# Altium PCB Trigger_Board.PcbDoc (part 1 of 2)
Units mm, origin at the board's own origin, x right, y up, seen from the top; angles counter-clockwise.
Board outline 80 x 80 mm, 4 copper layers (Component Side, Signal Layer 1, Signal Layer 2, Bottom Layer), stack 0.651 mm thick; 190 components, 73 nets, 468 pads, 398 vias.
Unrouted connection lines stored in the file: 444.
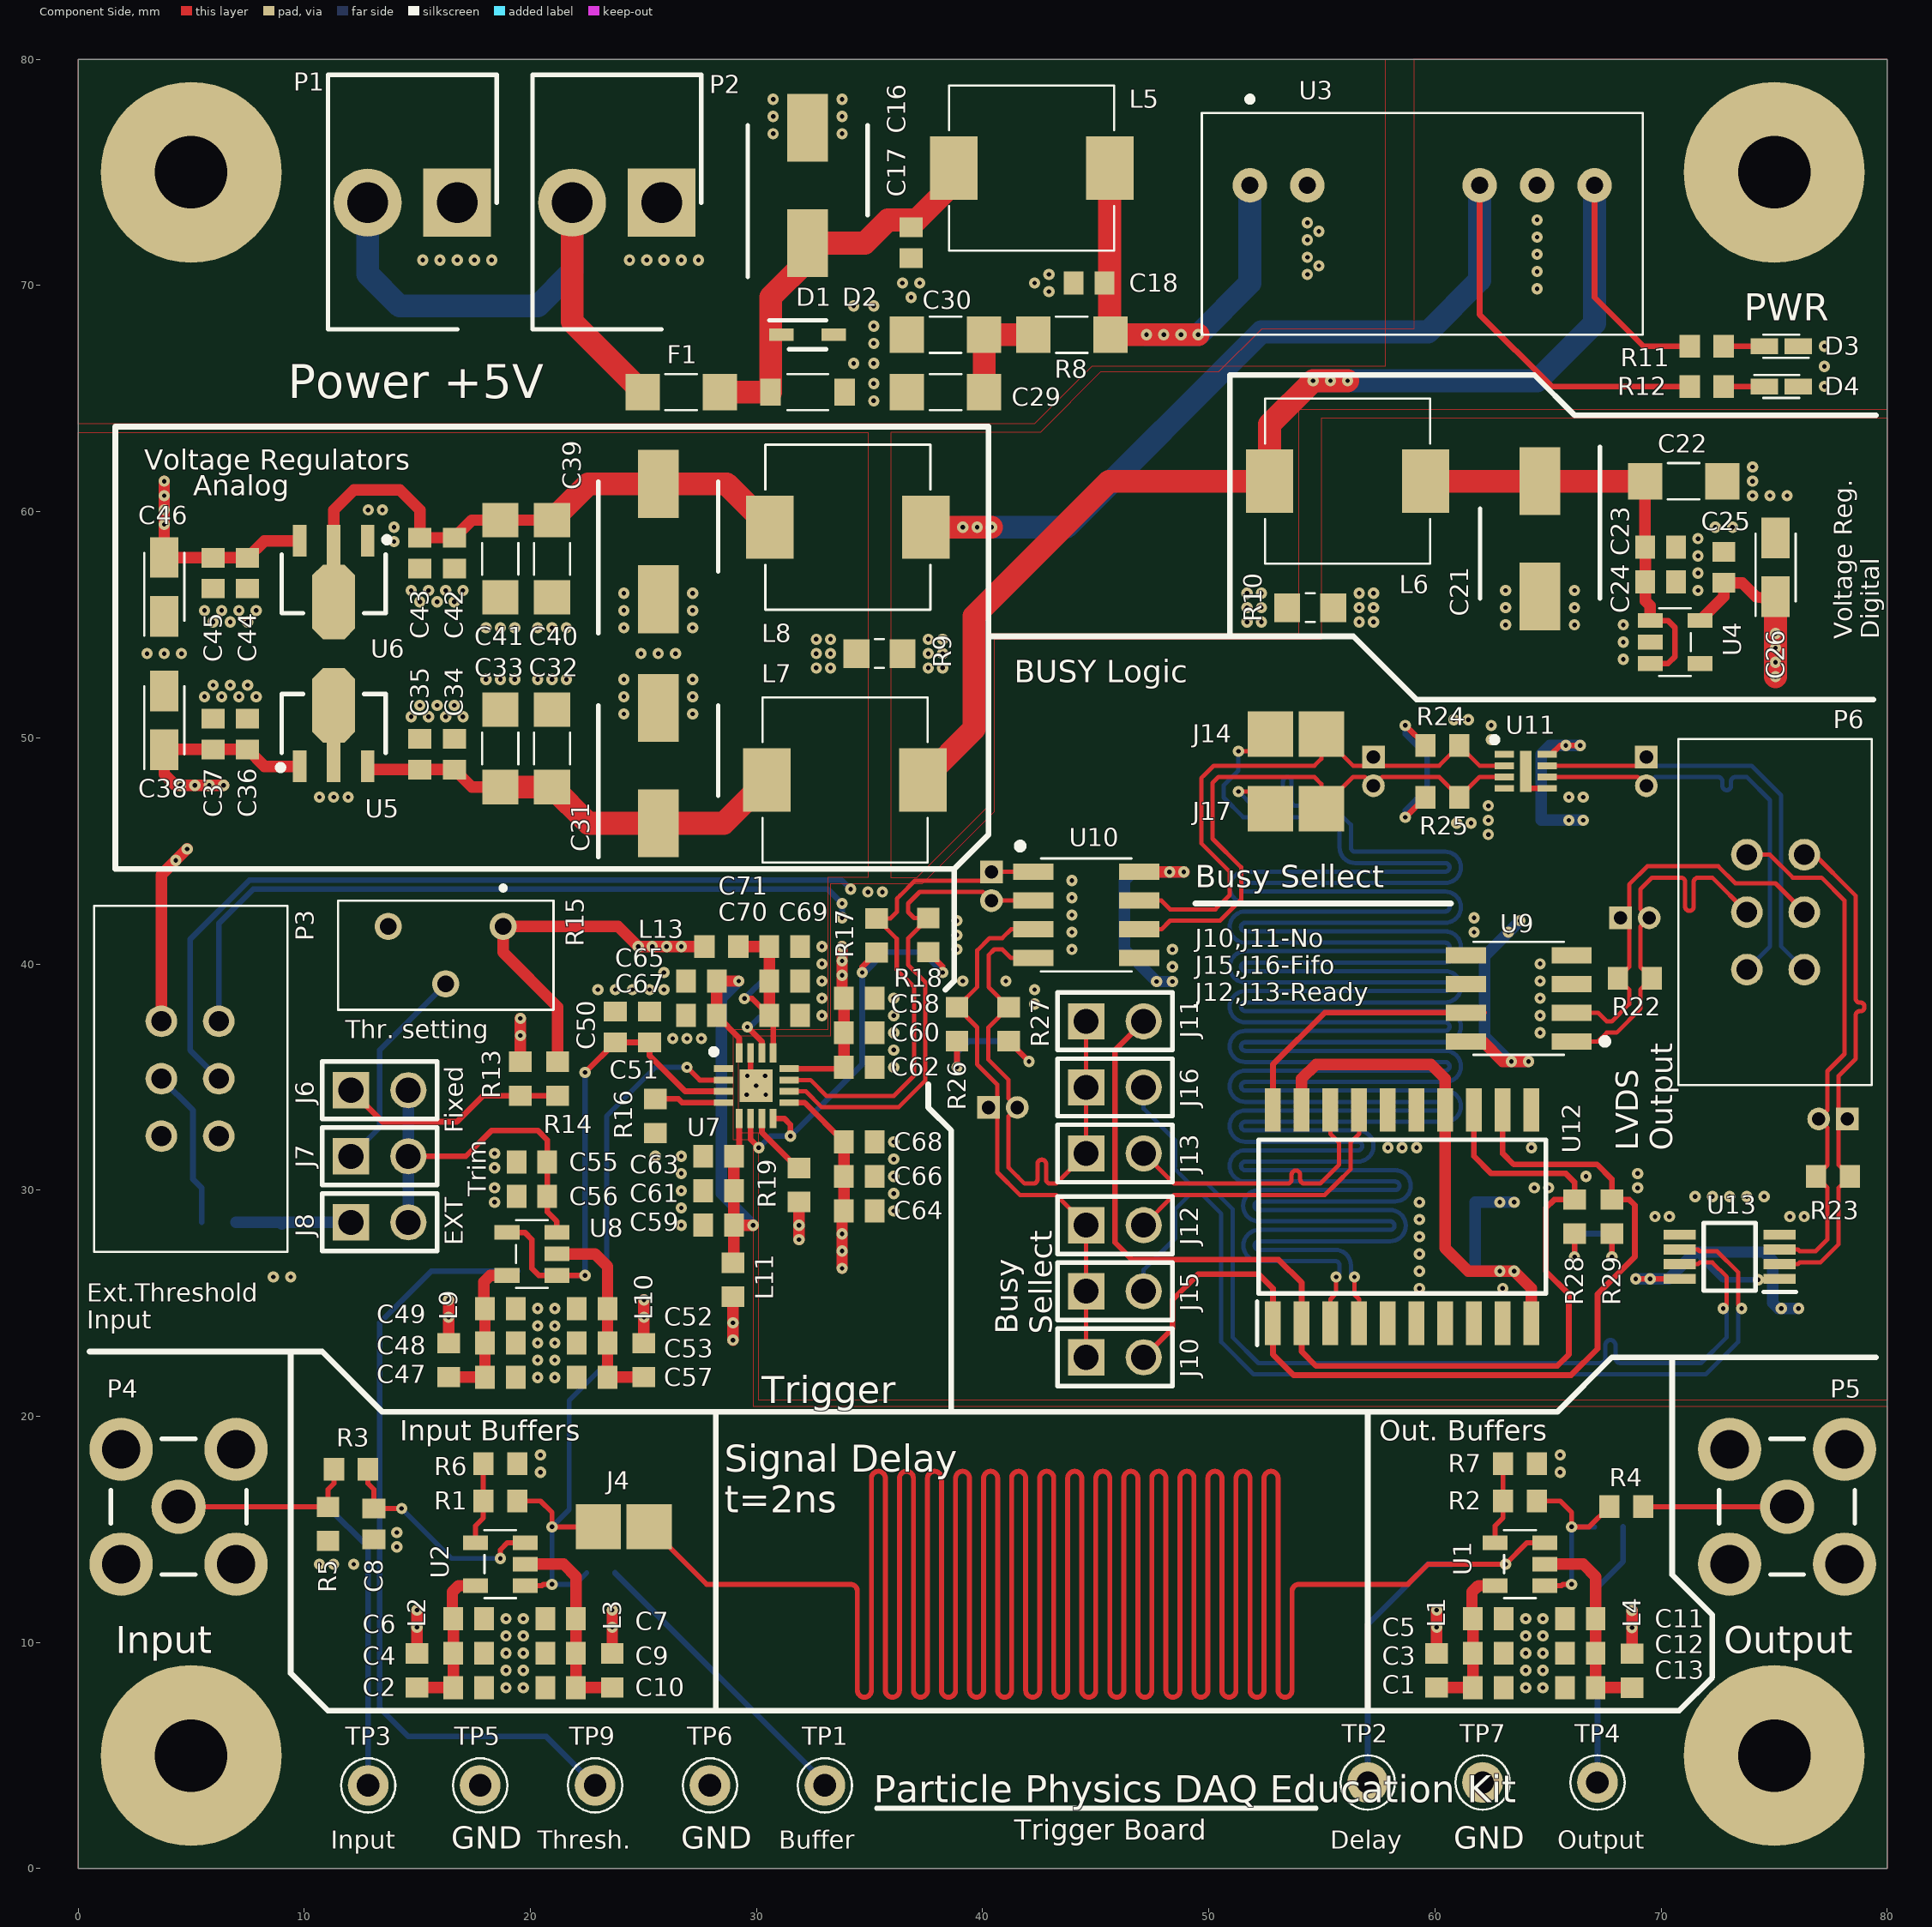
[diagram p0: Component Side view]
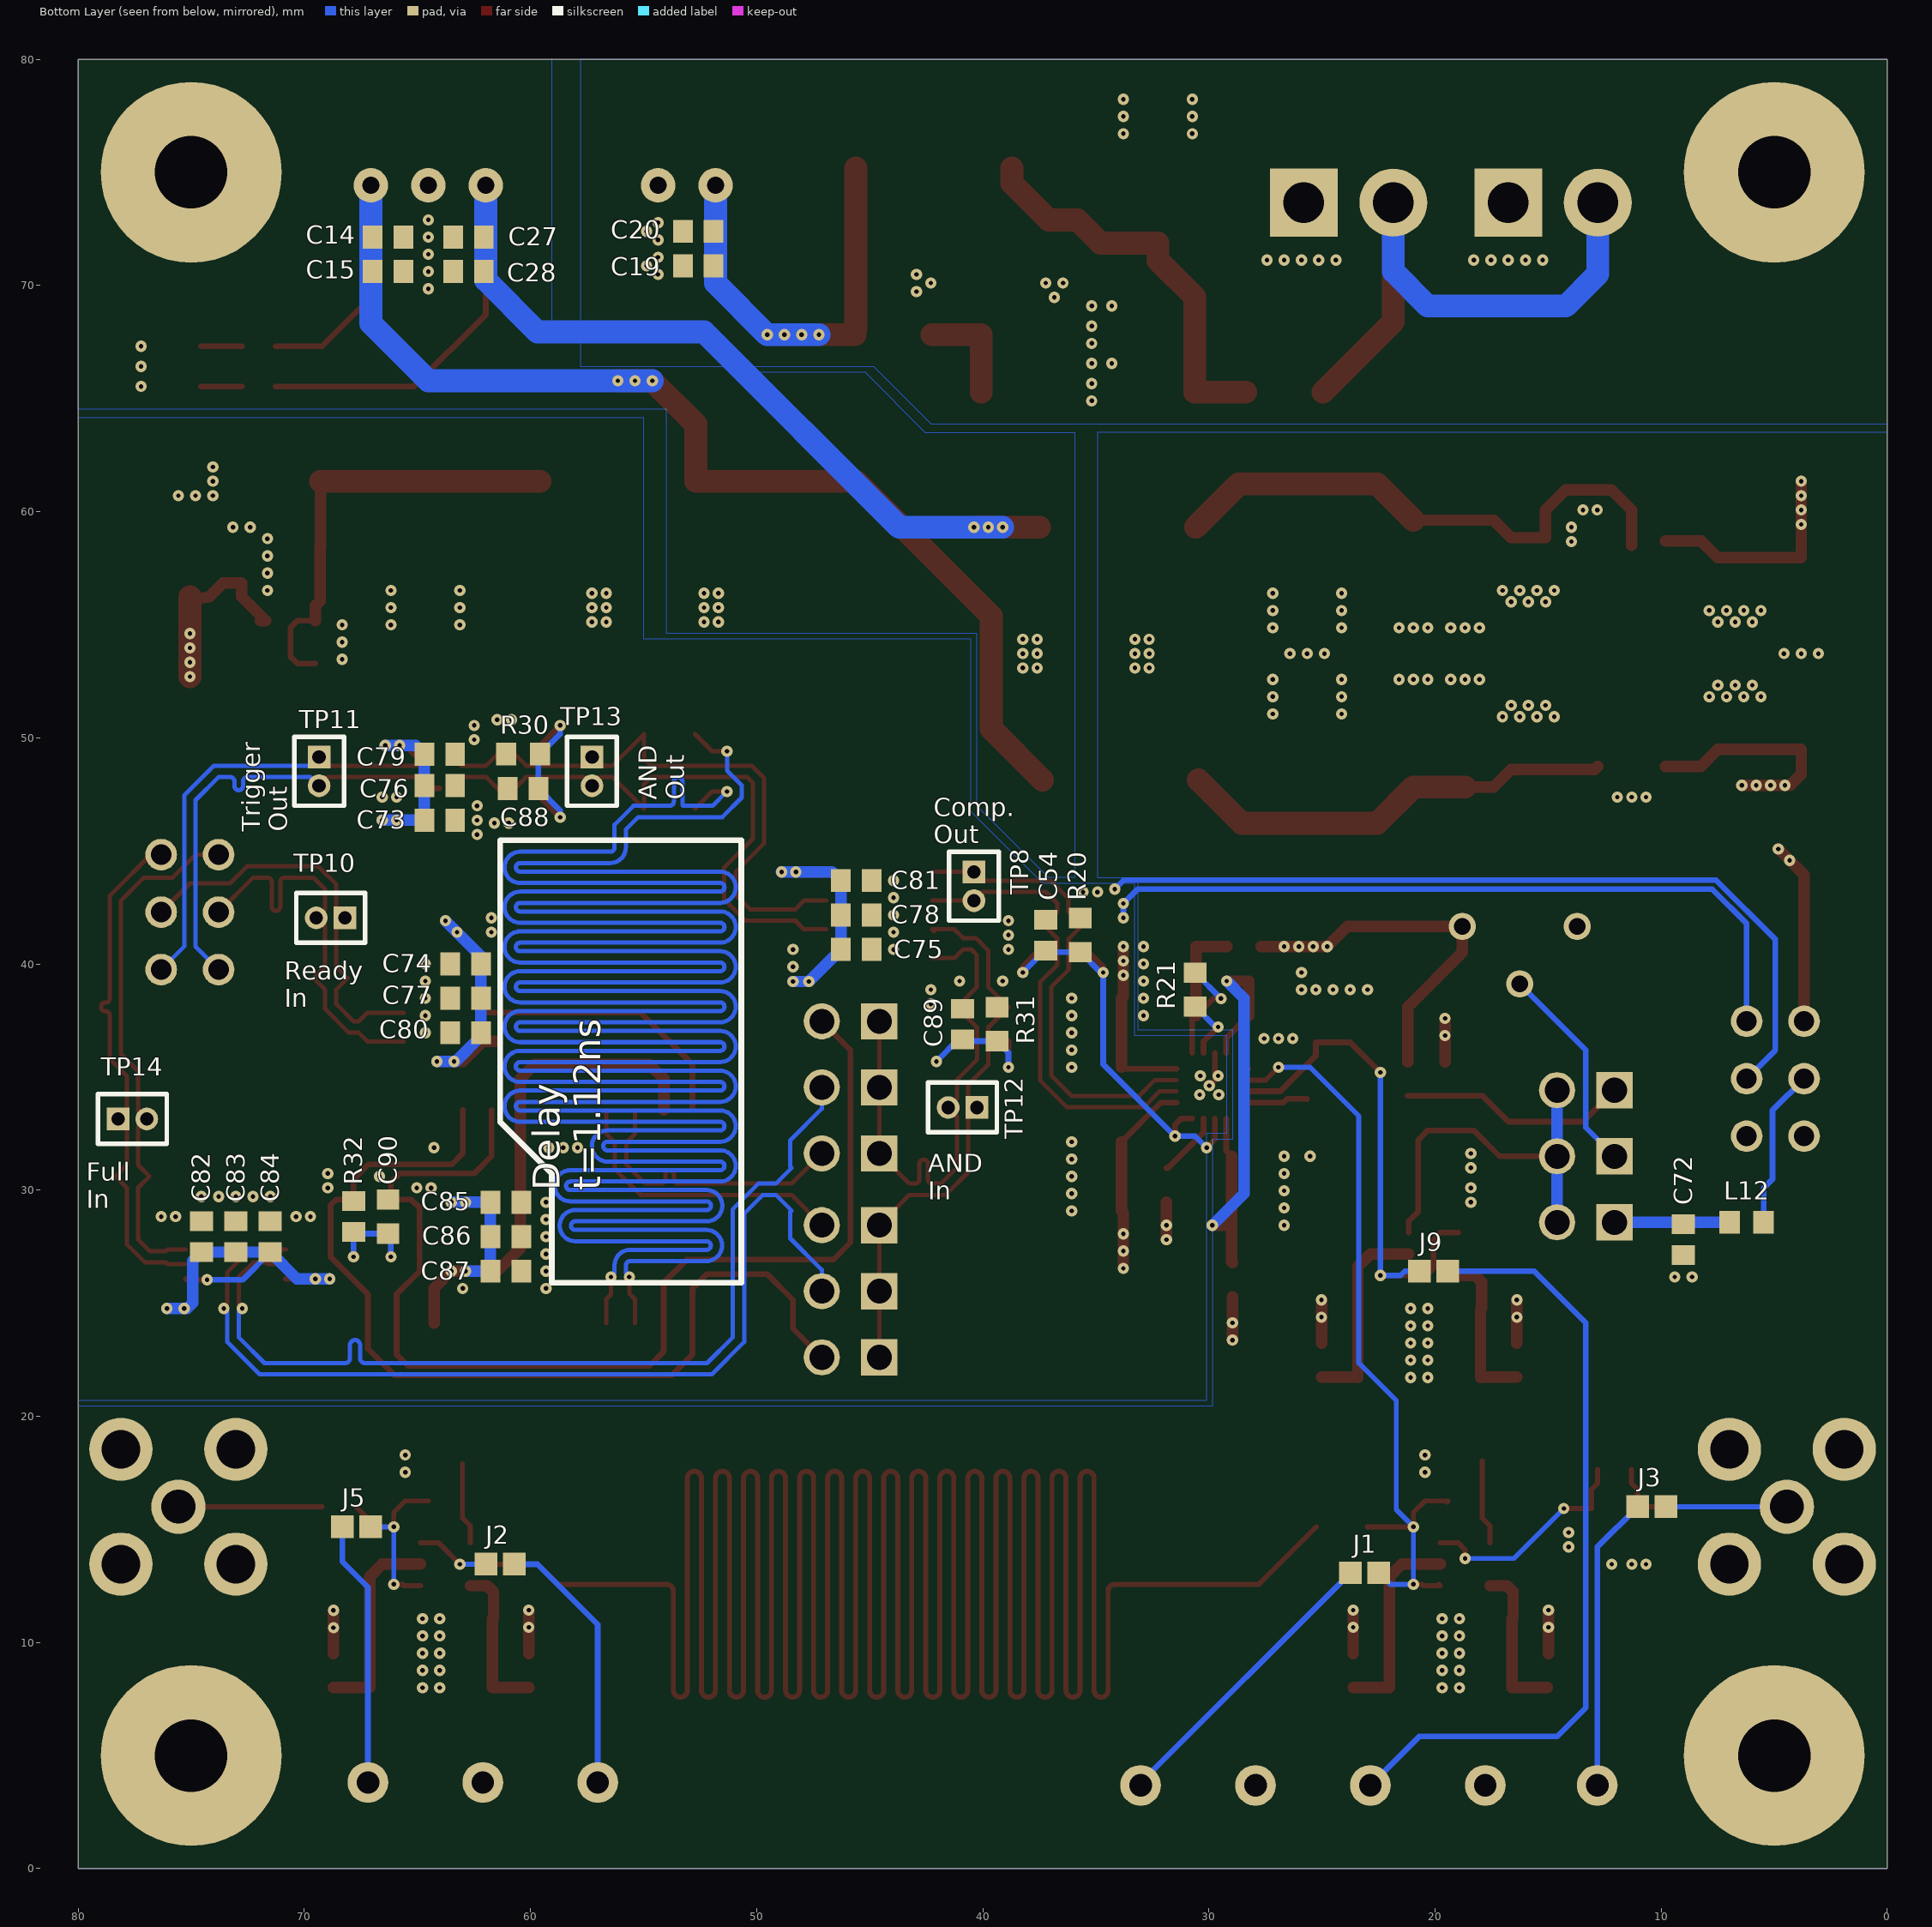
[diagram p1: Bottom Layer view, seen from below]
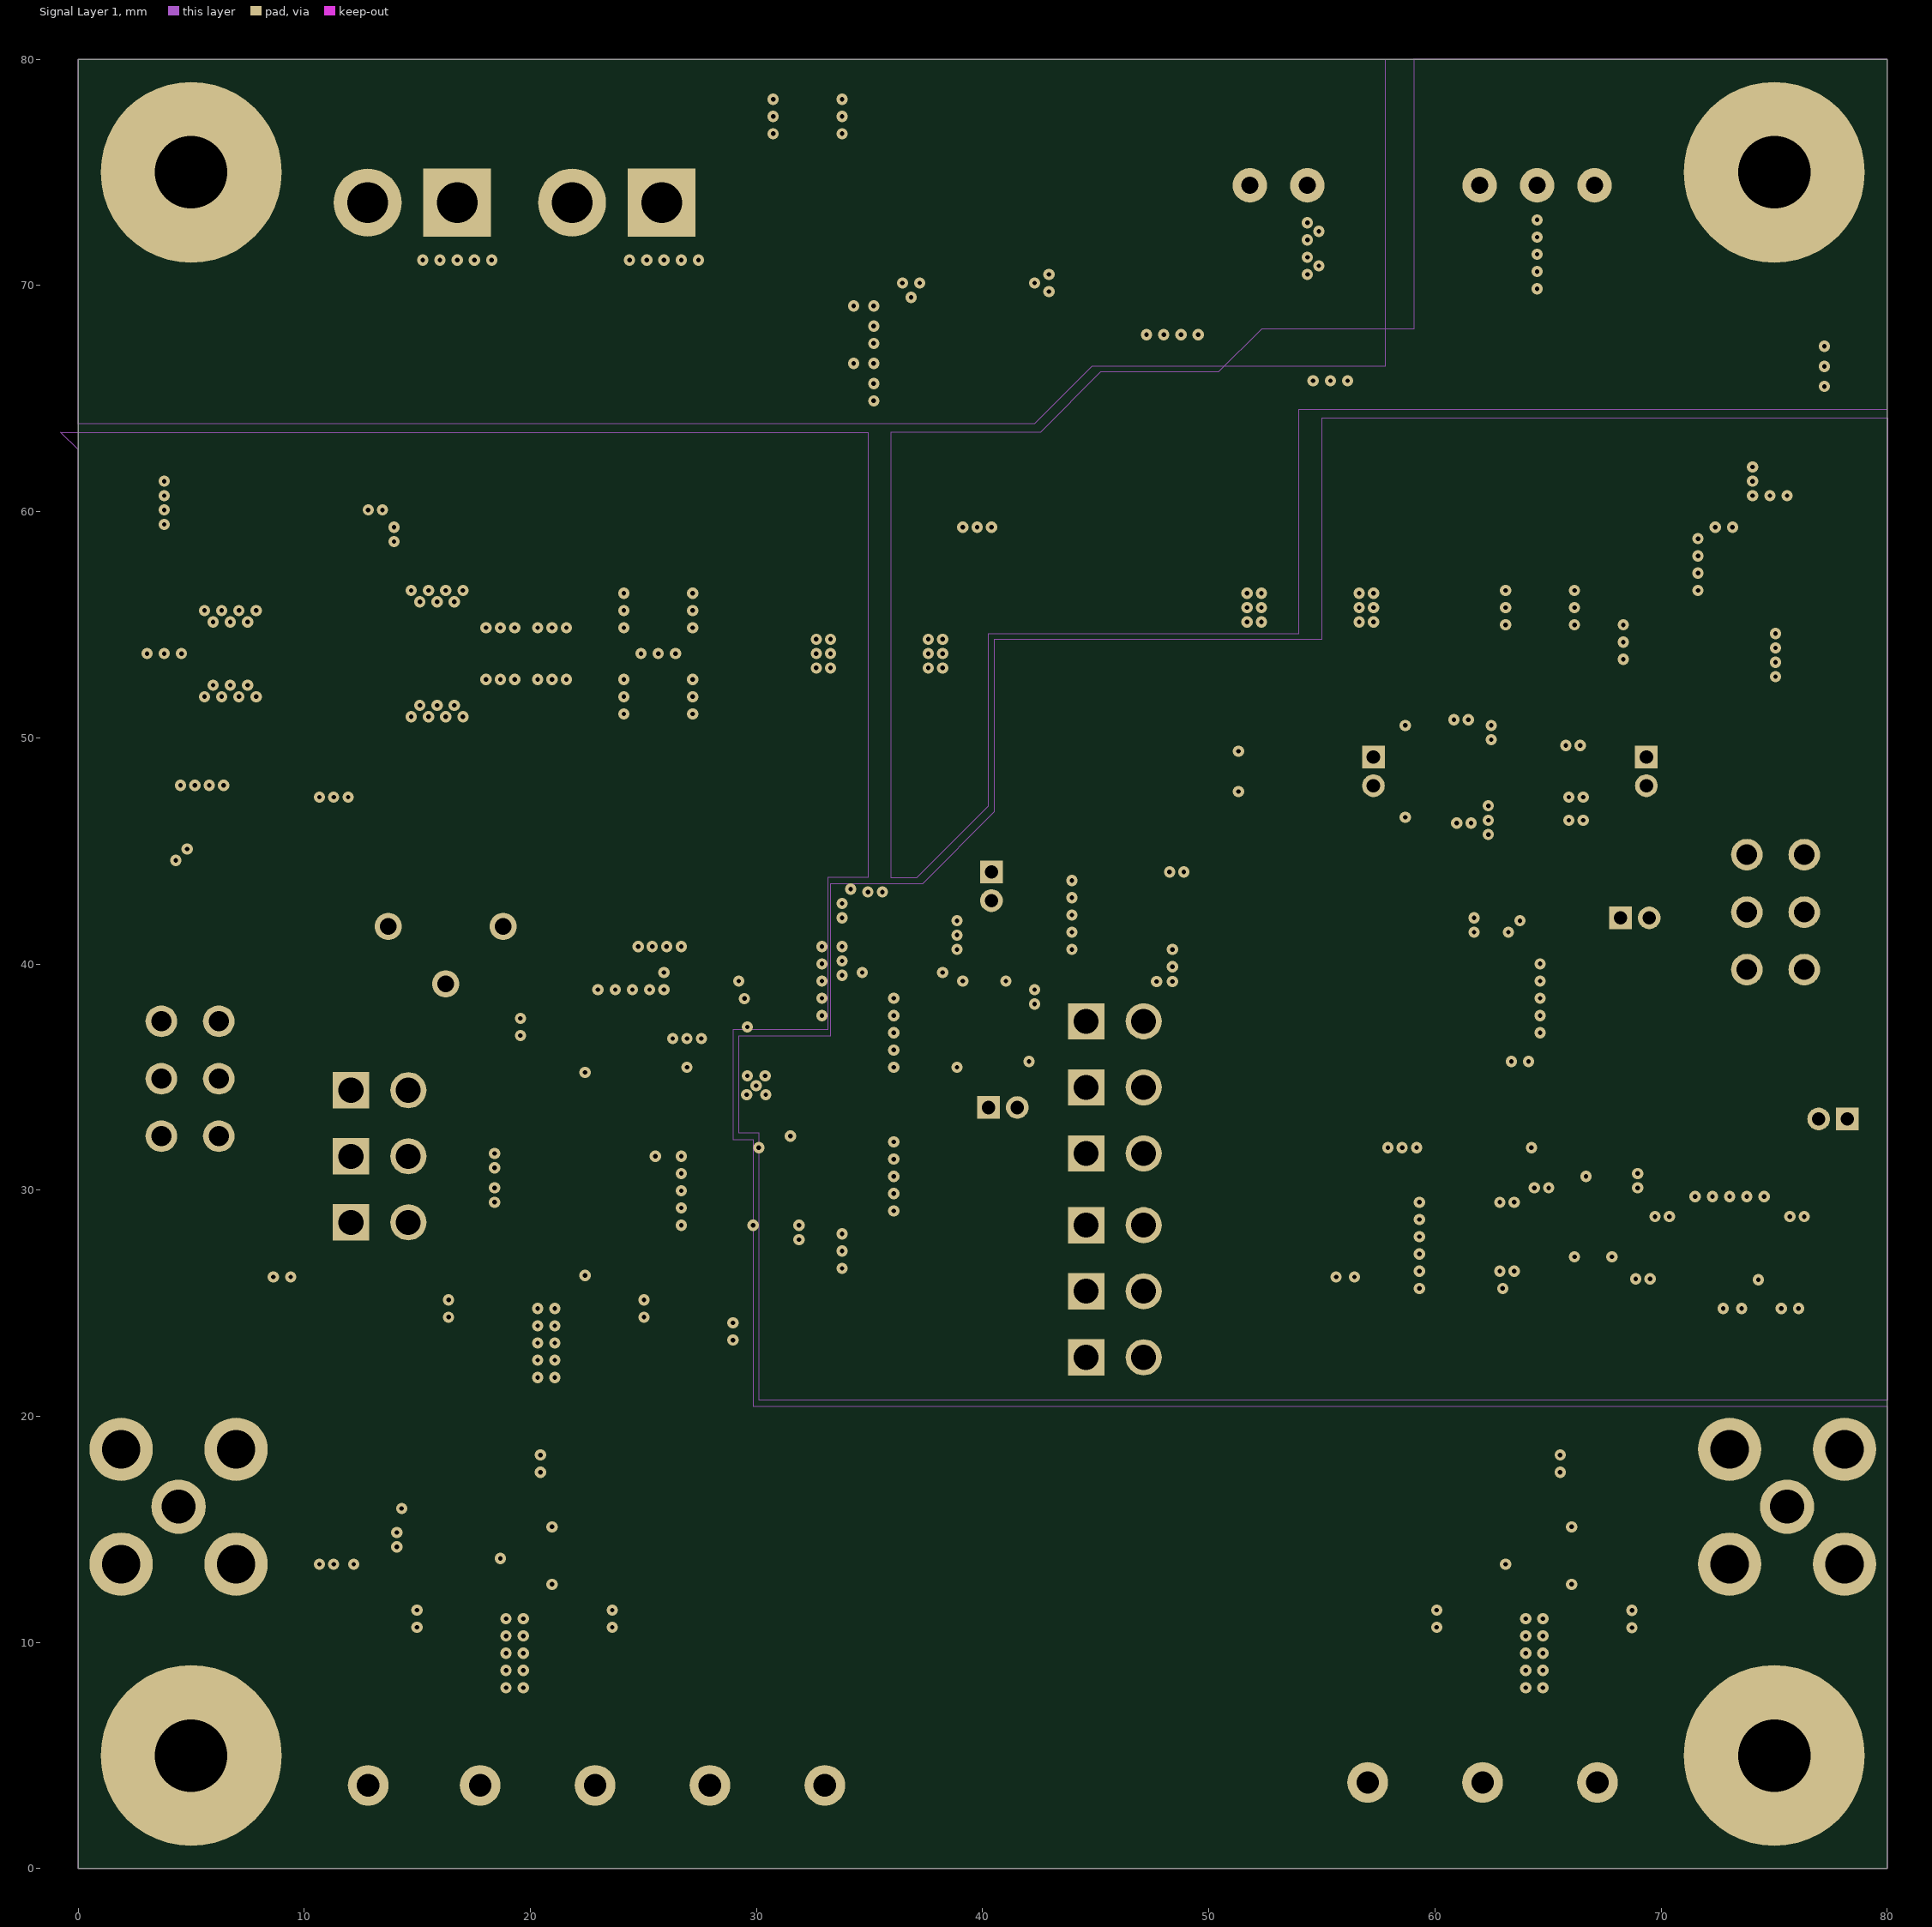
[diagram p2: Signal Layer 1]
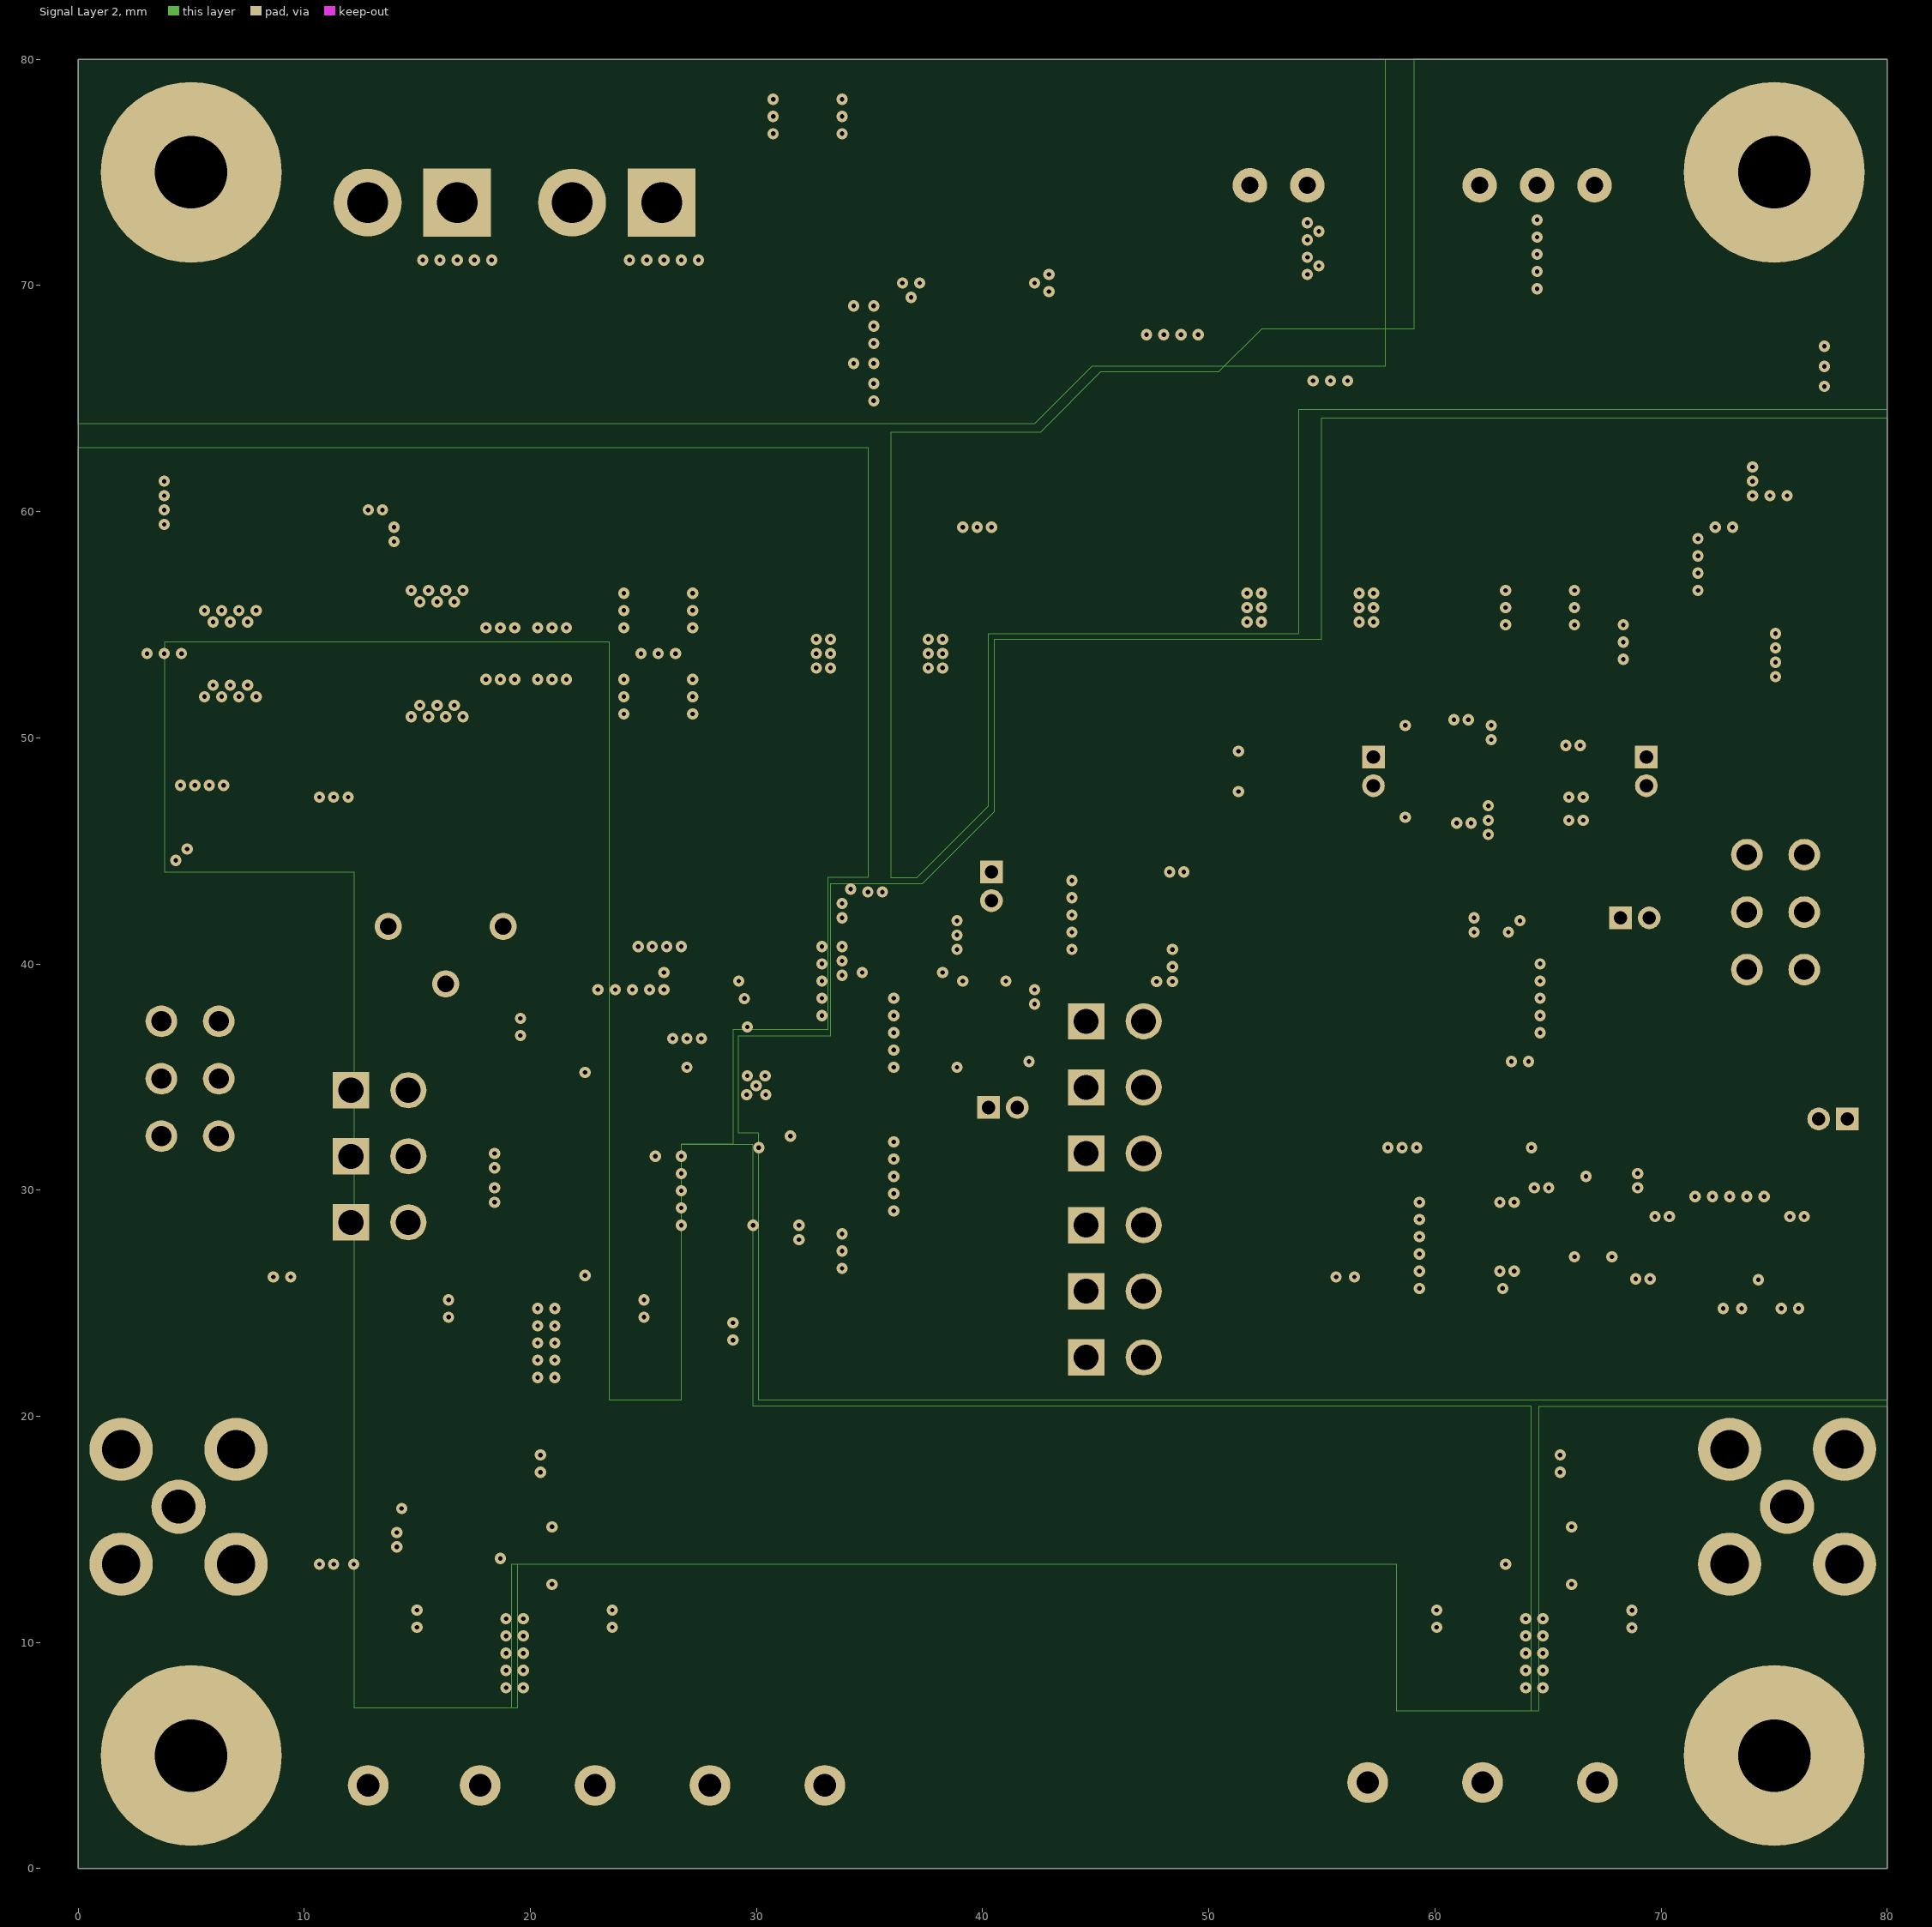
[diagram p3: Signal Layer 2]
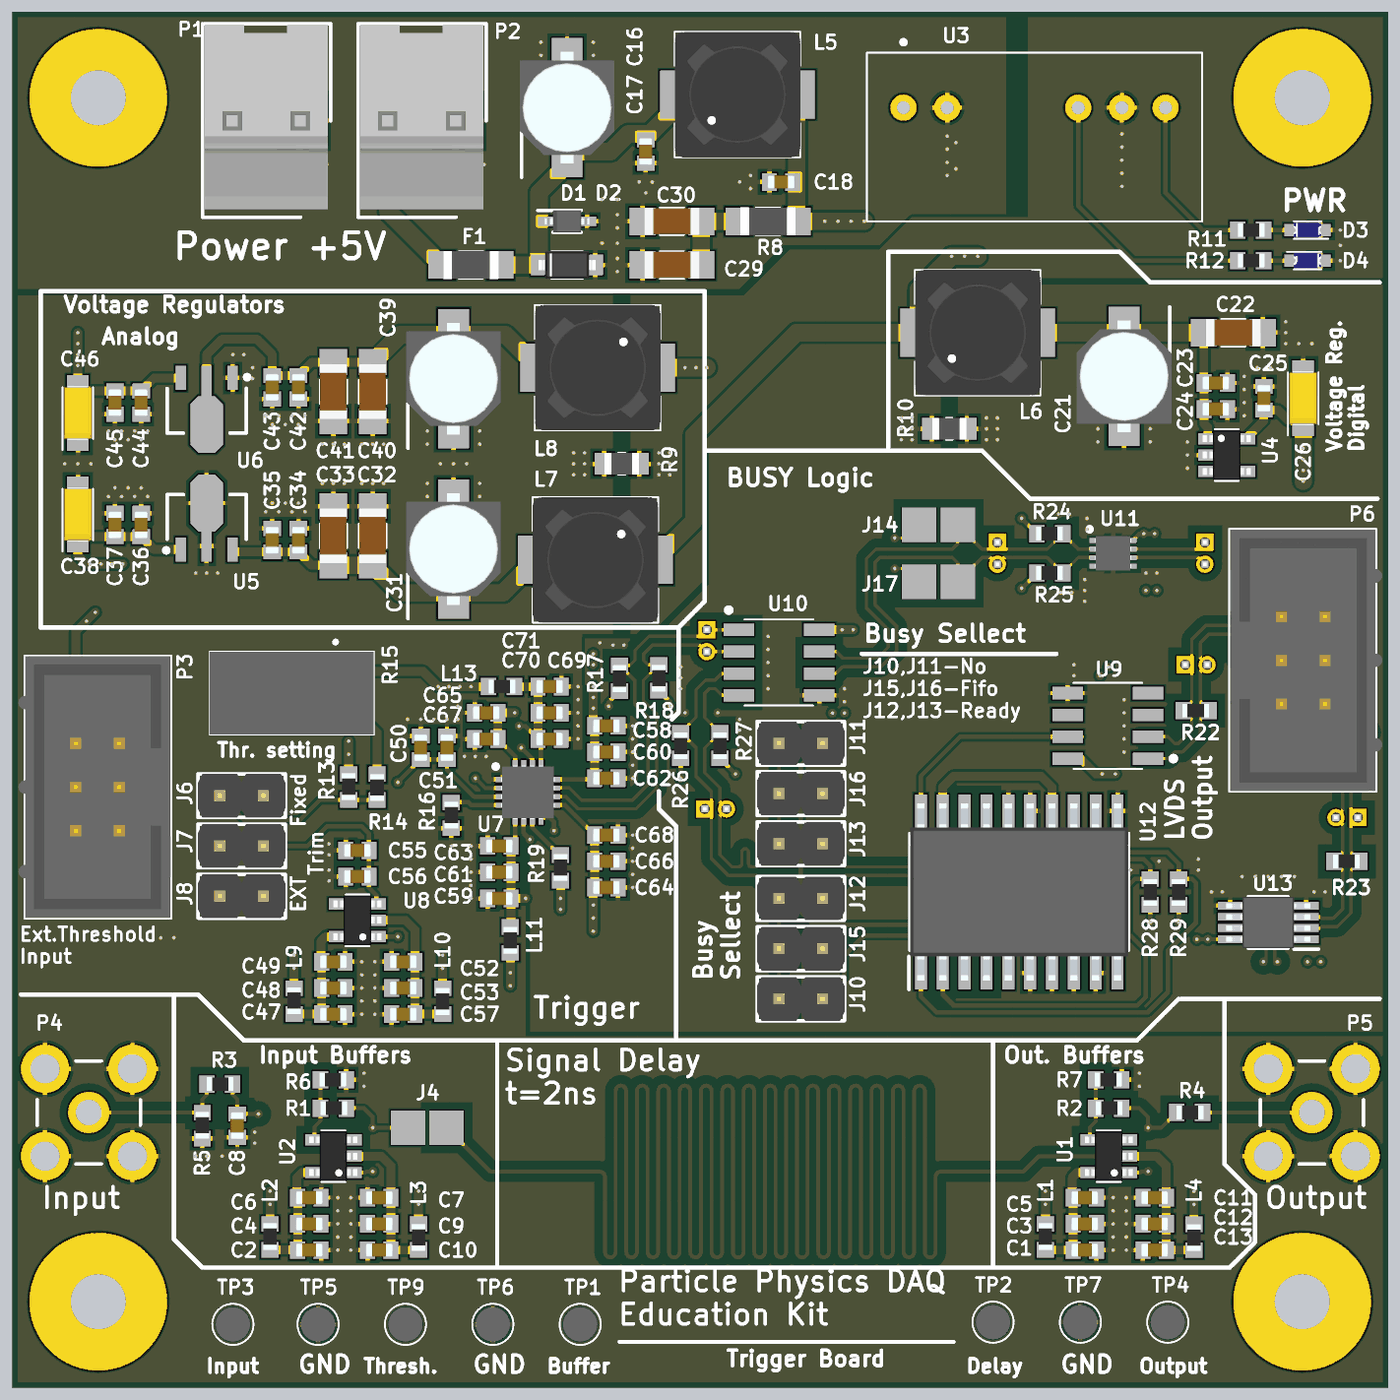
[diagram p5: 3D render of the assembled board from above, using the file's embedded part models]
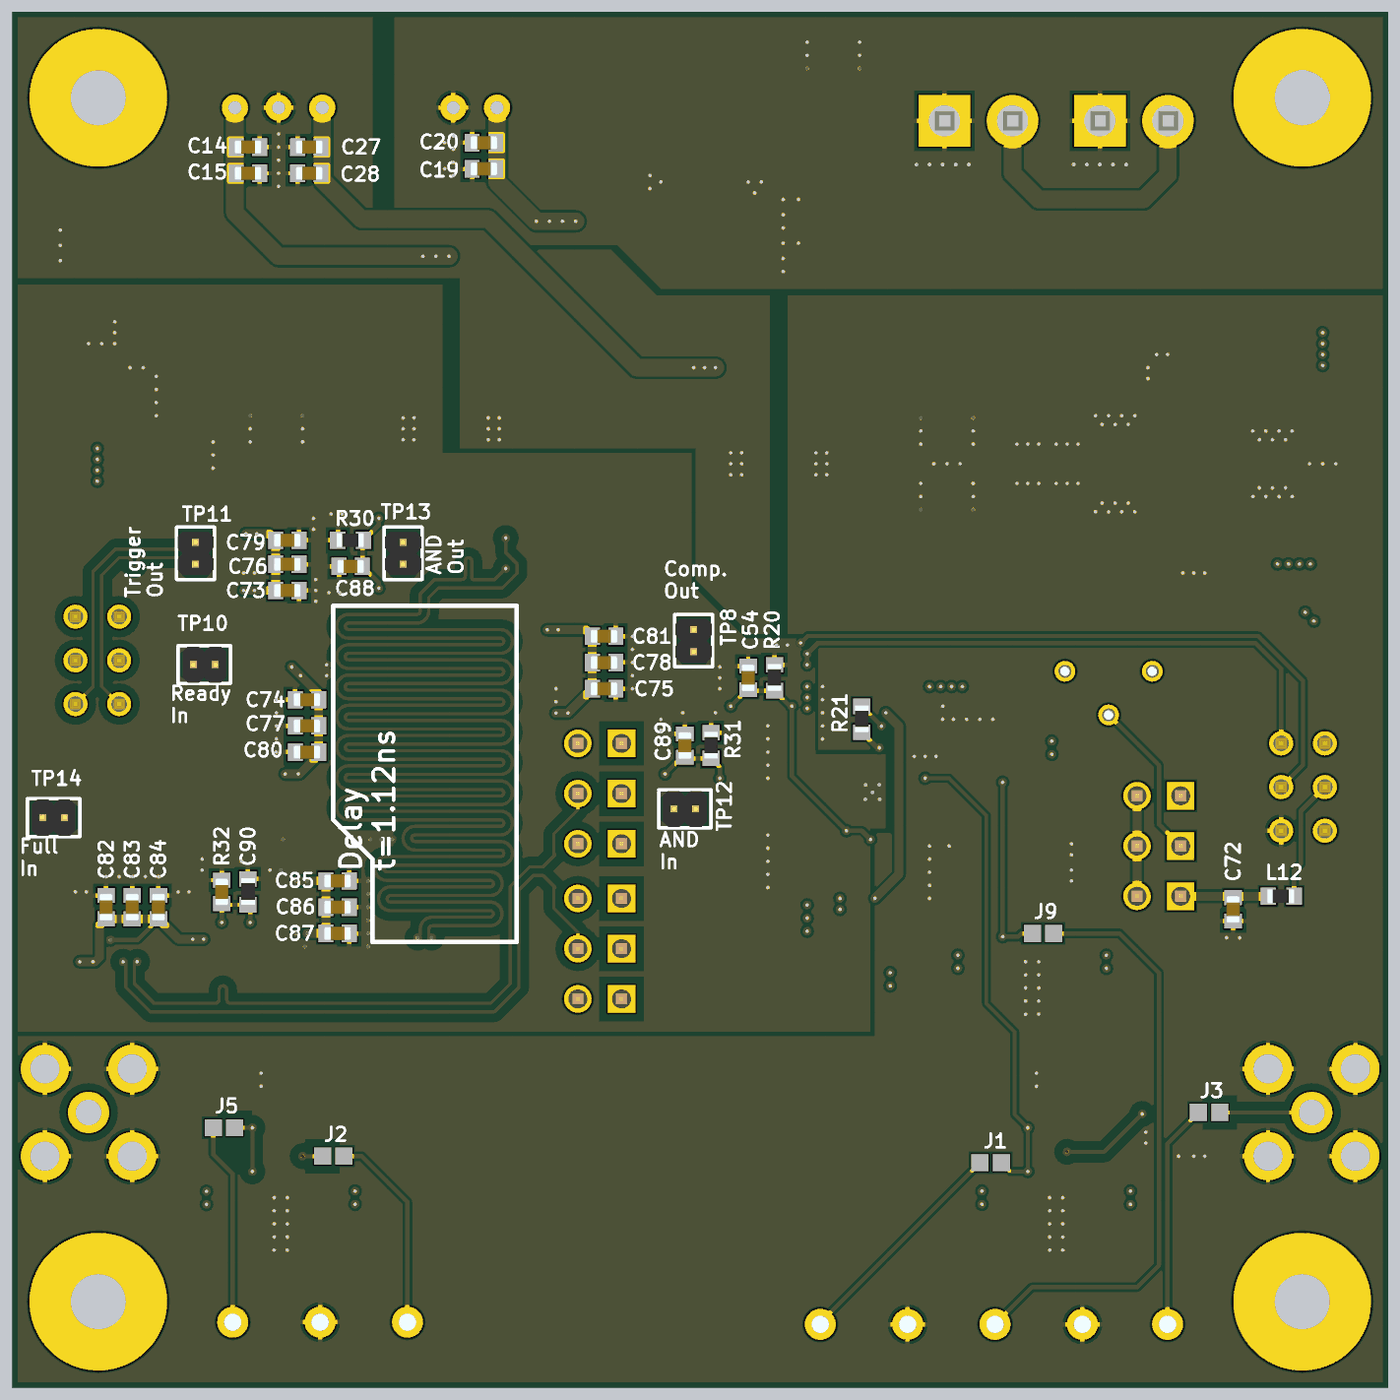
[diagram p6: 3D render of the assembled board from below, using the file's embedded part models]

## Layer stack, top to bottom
Top Solder: solder mask 0.0102, Solder Resist, Dk 3.5
Component Side: signal copper 0.0356
Dielectric 1: prepreg 0.127, FR-4, Dk 4.2
Signal Layer 1: signal copper 0.036
Dielectric 3: core 0.254, Dk 4.2
Signal Layer 2: signal copper 0.036
Dielectric 2: prepreg 0.127, Dk 4.2
Bottom Layer: signal copper 0.0356
Solder Side: solder mask 0.0102, Solder Resist, Dk 3.5

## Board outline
0,0 80,0 80,80 0,80

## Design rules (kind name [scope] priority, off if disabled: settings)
BoardOutlineClearance [All] p1: gap=0.3 ignorepadtopadclearanceinfootprint=FALSE
Clearance Clearance_DiffPair [(InDifferentialPairClass('All Differential Pairs') AND NOT InComponent('U13')  AND NOT InComponent('U9')  AND NOT InComponent('U11'))] p1: gap=0.15 ignorepadtopadclearanceinfootprint=FALSE except(0: Arc-Hole Track-Hole SMDPad-Hole THPad-Hole Via-Hole Fill-Hole Poly-Hole Region-Hole Text-Hole; 0.5: Arc-Poly Track-Poly SMDPad-Poly THPad-Poly Via-Poly Fill-Poly Poly-Poly)
Clearance Clearance_50R [(InNetClass('50R') AND NOT InComponent('U7') AND NOT InNet('NetJ1_1'))] p2: gap=0.15 ignorepadtopadclearanceinfootprint=FALSE except(0: Arc-Hole Track-Hole SMDPad-Hole THPad-Hole Via-Hole Fill-Hole Poly-Hole Region-Hole Text-Hole; 0.5: Arc-Fill Arc-Poly Arc-Region Track-Fill Track-Poly Track-Region SMDPad-Fill SMDPad-Poly SMDPad-Region THPad-Fill THPad-Poly THPad-Region Via-Fill Via-Poly Via-Region Fill-Fill Fill-Poly Fill-Region Poly-Poly Poly-Region Region-Region)
Clearance [All] p3: gap=0.15 ignorepadtopadclearanceinfootprint=FALSE except(0: Arc-Hole Track-Hole SMDPad-Hole THPad-Hole Via-Hole Fill-Hole Poly-Hole Region-Hole Text-Hole)
DiffPairsRouting [All] p1: maxlimit=0.31 minlimit=0.31 mostfreqgap=0.31 toplayer_minwidth=0.19 toplayer_maxwidth=0.19 toplayer_prefwidth=0.19 midlayer1_minwidth=0.19 midlayer1_maxwidth=0.19 midlayer1_prefwidth=0.19 midlayer2_minwidth=0.19 midlayer2_maxwidth=0.19 midlayer2_prefwidth=0.19 bottomlayer_minwidth=0.19 bottomlayer_maxwidth=0.19 bottomlayer_prefwidth=0.19 maxuncoupledlength=12.7
HoleSize [All] p1: absolutevalues=TRUE maxlimit=4 minlimit=0.025 maxpercent=80.000 minpercent=20.000
MatchedLengths [All] p1: tolerance=1 checknetsindiffpair=TRUE checkdiffpairvsdiffpair=FALSE checkxsignals=FALSE checkothers=FALSE
MinimumSolderMaskSliver [All] p1: minsoldermaskwidth=0.065
PolygonConnect [All] p1: thpad.connectstyle=Relief thpad.reliefconductorwidth=0.254 thpad.reliefentries=4 thpad.polygonreliefangle="90 Angle" thpad.airgapwidth=0.254 smdpad.connectstyle=Relief smdpad.reliefconductorwidth=0.254 smdpad.reliefentries=4 smdpad.polygonreliefangle="90 Angle" smdpad.airgapwidth=0.254 via.connectstyle=Direct via.reliefconductorwidth=0.254 via.reliefentries=4 via.polygonreliefangle="90 Angle" via.airgapwidth=0.254
RoutingVias [All] p1: holewidth=0.2 width=0.5 viastyle="Through Hole" minholewidth=0.2 minwidth=0.5 maxholewidth=0.2 maxwidth=0.5
SilkToSilkClearance [All] p1: silktosilkclearance=0.1
SilkToSolderMaskClearance [IsPad] p1: minsilkscreentomaskgap=0.1 clearancetoexposedcopper=TRUE
SolderMaskExpansion [All] p1: expansion=0.102
Width Width-50R [InNetClass('50R')] p1: maxlimit=0.22 minlimit=0.22 preferedwidth=0.22
Width [All] p2: maxlimit=1.016 minlimit=0.254 preferedwidth=0.508
25 further rules are at their usual default settings.

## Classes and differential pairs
net class 50R: NetC8_2 NetJ1_1 NetJ2_1 NetJ3_1 NetJ5_2 NetP5_1 NetR1_1 NetR2_1
component class U_Trigger: C47 C48 C49 C50 C51 C52 C53 C54 C55 C56 C57 C58 C59 C60 C61 C62 C63 C64 C65 C66 C67 C68 C69 C70 C71 C72 J6 J7 J8 J9 L9 L10 L11 L12 L13 P3 R13 R14 R15 R16 R17 R18 R19 R20 R21 TP8 TP9 U7 U8
component class U_Power: C14 C15 C16 C17 C18 C19 C20 C21 C22 C23 C24 C25 C26 C27 C28 C29 C30 C31 C32 C33 C34 C35 C36 C37 C38 C39 C40 C41 C42 C43 C44 C45 C46 D1 D2 D3 D4 F1 L5 L6 L7 L8 P1 P2 R8 R9 R10 R11 R12 U3 U4 U5 U6
component class U_Busy_Logic: C73 C74 C75 C76 C77 C78 C79 C80 C81 C82 C83 C84 C85 C86 C87 C88 C89 C90 J10 J11 J12 J13 J14 J15 J16 J17 R22 R23 R24 R25 R26 R27 R28 R29 R30 R31 R32 TP10 TP11 TP12 TP13 TP14 U9 U10 U11 U12 U13
component class U_Analog: C1 C2 C3 C4 C5 C6 C7 C8 C9 C10 C11 C12 C13 J1 J2 J3 J4 J5 L1 L2 L3 L4 R1 R2 R3 R4 R5 R6 R7 TP1 TP2 TP3 TP4 TP5 TP6 TP7 U1 U2
component class Main: P4 P5 P6
differential pair TRG_out: +TRG_out_P -TRG_out_N
differential pair Ready: +Ready_P -Ready_N
differential pair nFull: +nFull_P -nFull_N
differential pair Full: +Full_P -Full_N
differential pair DOut: +DOut_P -DOut_N
differential pair DIn: +DIn_P -DIn_N
differential pair Comp_Out: +Comp_Out_P -Comp_Out_N
differential pair AndOut: +AndOut_P -AndOut_N
differential pair AndIN: +AndIN_P -AndIN_N

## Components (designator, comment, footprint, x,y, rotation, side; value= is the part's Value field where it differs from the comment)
C1 "1u" SMD_CAPACITOR_0603 62.357,8.001 r0 top
C2 "1u" SMD_CAPACITOR_0603 17.272,8.001 r0 top
C3 "100nF" SMD_CAPACITOR_0603 62.357,9.525 r0 top
C4 "100nF" SMD_CAPACITOR_0603 17.272,9.525 r0 top
C5 "10nF" SMD_CAPACITOR_0603 62.357,11.049 r0 top
C6 "10nF" SMD_CAPACITOR_0603 17.272,11.049 r0 top
C7 "10nF" SMD_CAPACITOR_0603 21.336,11.049 r180 top
C8 "D.N.P." SMD_CAPACITOR_0603 13.081,15.24 r90 top
C9 "100nF" SMD_CAPACITOR_0603 21.336,9.525 r180 top
C10 "1u" SMD_CAPACITOR_0603 21.336,8.001 r180 top
C11 "10nF" SMD_CAPACITOR_0603 66.421,11.049 r180 top
C12 "100nF" SMD_CAPACITOR_0603 66.421,9.525 r180 top
C13 "1u" SMD_CAPACITOR_0603 66.421,8.001 r180 top
C14 "100n" SMD_CAPACITOR_0603 66.294,72.136 r0 bottom
C15 "1u" SMD_CAPACITOR_0603 66.294,70.612 r0 bottom
C16 "10u" SMD_CAP_POL_D5.0mm 32.258,74.422 r90 top
C17 "100n" SMD_CAPACITOR_0603 36.83,71.882 r90 top
C18 "100n" SMD_CAPACITOR_0603 44.704,70.104 r0 top
C19 "1u" SMD_CAPACITOR_0603 52.578,70.866 r180 bottom
C20 "100n" SMD_CAPACITOR_0603 52.578,72.39 r180 bottom
C21 "10u" SMD_CAP_POL_D5.0mm 64.643,58.801 r270 top
C22 "10u" SMD_CAPACITOR_1206 70.993,61.341 r180 top
C23 "100n" SMD_CAPACITOR_0603 69.977,58.42 r180 top
C24 "10n" SMD_CAPACITOR_0603 69.977,56.896 r180 top
C25 "100n" SMD_CAPACITOR_0603 72.771,57.531 r270 top
C26 "1u" SMD_CAPACITOR_POL_A_3216 75.057,57.531 r90 top
C27 "100n" SMD_CAPACITOR_0603 62.738,72.136 r0 bottom
C28 "1u" SMD_CAPACITOR_0603 62.738,70.612 r0 bottom
C29 "10u" SMD_CAPACITOR_1206 38.354,65.278 r0 top
C30 "10u" SMD_CAPACITOR_1206 38.354,67.818 r0 top
C31 "10u" SMD_CAP_POL_D5.0mm 25.654,48.768 r90 top
C32 "10u" SMD_CAPACITOR_1206 20.955,49.53 r270 top
C33 "D.N.P." SMD_CAPACITOR_1206 18.669,49.53 r270 top
C34 "100n" SMD_CAPACITOR_0603 16.637,49.276 r270 top
C35 "D.N.P." SMD_CAPACITOR_0603 15.113,49.276 r270 top
C36 "D.N.P." SMD_CAPACITOR_0603 7.493,50.165 r270 top
C37 "100n" SMD_CAPACITOR_0603 5.969,50.165 r270 top
C38 "1u" SMD_CAPACITOR_POL_A_3216 3.81,50.77 r90 top
C39 "10u" SMD_CAP_POL_D5.0mm 25.654,58.674 r90 top
C40 "10u" SMD_CAPACITOR_1206 20.955,57.912 r90 top
C41 "D.N.P." SMD_CAPACITOR_1206 18.669,57.912 r90 top
C42 "100n" SMD_CAPACITOR_0603 16.637,58.166 r90 top
C43 "D.N.P." SMD_CAPACITOR_0603 15.113,58.166 r90 top
C44 "D.N.P." SMD_CAPACITOR_0603 7.493,57.277 r90 top
C45 "100n" SMD_CAPACITOR_0603 5.969,57.277 r90 top
C46 "1u" SMD_CAPACITOR_POL_A_3216 3.81,56.672 r90 top
C47 "1u" SMD_CAPACITOR_0603 18.669,21.717 r0 top
C48 "100nF" SMD_CAPACITOR_0603 18.669,23.241 r0 top
C49 "10nF" SMD_CAPACITOR_0603 18.669,24.765 r0 top
C50 "1uF" SMD_CAPACITOR_0603 23.749,37.211 r270 top
C51 "100nF" SMD_CAPACITOR_0603 25.273,37.211 r270 top
C52 "10nF" SMD_CAPACITOR_0603 22.733,24.765 r180 top
C53 "100nF" SMD_CAPACITOR_0603 22.733,23.241 r180 top
C54 "10n" SMD_CAPACITOR_0603 37.211,41.275 r270 bottom
C55 "1uF" SMD_CAPACITOR_0603 20.066,31.242 r0 top
C56 "100nF" SMD_CAPACITOR_0603 20.066,29.718 r0 top
C57 "1u" SMD_CAPACITOR_0603 22.733,21.717 r180 top
C58 "1u" SMD_CAPACITOR_0603 34.544,38.481 r0 top
C59 "1u" SMD_CAPACITOR_0603 28.321,28.448 r180 top
C60 "100nF" SMD_CAPACITOR_0603 34.544,36.957 r0 top
C61 "100nF" SMD_CAPACITOR_0603 28.321,29.972 r180 top
C62 "10nF" SMD_CAPACITOR_0603 34.544,35.433 r0 top
C63 "10nF" SMD_CAPACITOR_0603 28.321,31.496 r180 top
C64 "1u" SMD_CAPACITOR_0603 34.544,29.083 r0 top
C65 "100nF" SMD_CAPACITOR_0603 27.559,39.243 r180 top
C66 "100nF" SMD_CAPACITOR_0603 34.544,30.607 r0 top
C67 "10nF" SMD_CAPACITOR_0603 27.559,37.719 r180 top
C68 "10nF" SMD_CAPACITOR_0603 34.544,32.131 r0 top
C69 "10nF" SMD_CAPACITOR_0603 31.242,37.719 r0 top
C70 "100nF" SMD_CAPACITOR_0603 31.242,39.243 r0 top
C71 "1u" SMD_CAPACITOR_0603 31.242,40.767 r0 top
C72 "100nF" SMD_CAPACITOR_0603 9.017,27.813 r90 bottom
C73 "D.N.P." SMD_CAPACITOR_0603 64.008,46.355 r180 bottom
C74 "D.N.P." SMD_CAPACITOR_0603 62.865,40.005 r0 bottom
C75 "D.N.P." SMD_CAPACITOR_0603 45.593,40.64 r180 bottom
C76 "100nF" SMD_CAPACITOR_0603 64.008,47.879 r180 bottom
C77 "100nF" SMD_CAPACITOR_0603 62.865,38.481 r0 bottom
C78 "100nF" SMD_CAPACITOR_0603 45.593,42.164 r180 bottom
C79 "10nF" SMD_CAPACITOR_0603 64.008,49.276 r180 bottom
C80 "10nF" SMD_CAPACITOR_0603 62.865,36.957 r0 bottom
C81 "10nF" SMD_CAPACITOR_0603 45.593,43.688 r180 bottom
C82 "D.N.P." SMD_CAPACITOR_0603 74.549,27.94 r90 bottom
C83 "100nF" SMD_CAPACITOR_0603 73.025,27.94 r90 bottom
C84 "10nF" SMD_CAPACITOR_0603 71.501,27.94 r90 bottom
C85 "D.N.P." SMD_CAPACITOR_0603 61.087,29.464 r180 bottom
C86 "100nF" SMD_CAPACITOR_0603 61.087,27.94 r180 bottom
C87 "10nF" SMD_CAPACITOR_0603 61.087,26.416 r180 bottom
C88 "10n" SMD_CAPACITOR_0603 60.325,47.752 r180 bottom
C89 "10n" SMD_CAPACITOR_0603 40.894,37.338 r270 bottom
C90 "10n" SMD_CAPACITOR_0603 67.818,28.829 r270 bottom
D1 "1N4148W" SMD_SOD-123 32.258,65.278 r180 top
D2 "SD05.TCT" SMD_SOD-323 32.258,67.818 r0 top
D3 "GREEN" SMD_LED_0603 75.311,67.31 r180 top
D4 "GREEN" SMD_LED_0603 75.311,65.532 r0 top
F1 "Fuse" SMD_RESISTOR_1206 26.67,65.278 r0 top
J1 "SB" SOLDER_BRIDGE_1MM 23.114,13.081 r0 bottom
J2 "SB" SOLDER_BRIDGE_1MM 61.341,13.462 r180 bottom
J3 "SB" SOLDER_BRIDGE_1MM 10.414,16.002 r0 bottom
J4 "SB" SOLDER_BRIDGE_2MM 24.13,15.113 r0 top
J5 "SB" SOLDER_BRIDGE_1MM 67.691,15.113 r180 bottom
J6 "Header_2pin_1row" 61300211121 12.065,34.417 r0 top
J7 "Header_2pin_1row" 61300211121 12.065,31.496 r0 top
J8 "Header_2pin_1row" 61300211121 12.065,28.575 r0 top
J9 "SB" SOLDER_BRIDGE_1MM 20.066,26.416 r0 bottom
J10 "Header_2pin_1row" 61300211121 44.577,22.606 r0 top
J11 "Header_2pin_1row" 61300211121 44.577,37.465 r0 top
J12 "Header_2pin_1row" 61300211121 44.577,28.448 r0 top
J13 "Header_2pin_1row" 61300211121 44.577,31.623 r0 top
J14 "SB" SOLDER_BRIDGE_2MM 53.848,50.165 r0 top
J15 "Header_2pin_1row" 61300211121 44.577,25.527 r0 top
J16 "Header_2pin_1row" 61300211121 44.577,34.544 r0 top
J17 "SB" SOLDER_BRIDGE_2MM 53.848,46.863 r0 top
L1 "1k@100MHz" SMD_RES_0603 60.071,8.763 r90 top
L2 "1k@100MHz" SMD_RES_0603 14.986,8.763 r90 top
L3 "1k@100MHz" SMD_RES_0603 23.622,8.763 r270 top
L4 "1k@100MHz" SMD_RES_0603 68.707,8.751 r270 top
L5 "47uH" SMD_INDUCTOR_7.3MM 42.164,75.184 r0 top
L6 "220uH" SMD_INDUCTOR_7.3MM 56.134,61.341 r0 top
L7 "220uH" SMD_INDUCTOR_7.3MM 33.909,48.133 r180 top
L8 "220uH" SMD_INDUCTOR_7.3MM 34.036,59.309 r180 top
L9 "1k@100MHz" SMD_RES_0603 16.383,22.479 r90 top
L10 "1k@100MHz" SMD_RES_0603 25.019,22.479 r270 top
L11 "1k@100MHz" SMD_RES_0603 28.956,26.035 r270 top
L12 "1k@100MHz" SMD_RES_0603 6.223,28.575 r0 bottom
L13 "1k@100MHz" SMD_RES_0603 28.448,40.767 r0 top
P1 "09-65-2028" SHDR2W165P0X396_1X2_716X1062X1425P 16.764,73.66 r180 top
P2 "09-65-2028" SHDR2W165P0X396_1X2_716X1062X1425P 25.804,73.66 r180 top
P3 "Header 2x3" THT_HEADER_100MIL_2X3_MALE_SHROUDED 4.953,34.925 r0 top
P4 "SMA_Female" SMA5.08-H 4.445,16.002 r0 top
P5 "SMA_Female" SMA5.08-H 75.565,16.002 r180 top
P6 "Header 2x3" THT_HEADER_100MIL_2X3_MALE_SHROUDED 75.057,42.291 r180 top
R1 "0" SMD_RES_0603 18.669,16.256 r0 top
R2 "D.N.P." SMD_RES_0603 63.754,16.256 r0 top
R3 "0" SMD_RES_0603 12.065,17.653 r0 top
R4 "49.9" SMD_RES_0603 68.453,16.002 r0 top
R5 "49.9" SMD_RES_0603 11.049,15.24 r90 top
R6 "D.N.P." SMD_RES_0603 18.669,17.907 r180 top
R7 "0" SMD_RES_0603 63.754,17.907 r180 top
R8 "6R8" SMD_RESISTOR_1206 43.942,67.818 r0 top
R9 "0" SMD_RESISTOR_0805 35.433,53.721 r180 top
R10 "0" SMD_RESISTOR_0805 54.483,55.753 r0 top
R11 "1k2" SMD_RES_0603 72.009,67.31 r0 top
R12 "1k2" SMD_RES_0603 72.009,65.532 r0 top
R13 "1k" SMD_RES_0603 19.558,34.925 r90 top
R14 "2k7" SMD_RES_0603 21.209,34.925 r270 top
R15 "10k" THT_TRIM_3296Y1502LF 18.796,41.656 r90 top
R16 "D.N.P." SMD_RES_0603 25.527,33.274 r90 top
R17 "50" SMD_RES_0603 35.306,41.257 r270 top
R18 "50" SMD_RES_0603 37.592,41.275 r270 top
R19 "D.N.P." SMD_RES_0603 31.877,30.226 r90 top
R20 "50" SMD_RES_0603 35.687,41.275 r90 bottom
R21 "D.N.P." SMD_RES_0603 30.607,38.862 r90 bottom
R22 "100" SMD_RES_0603 68.834,39.37 r180 top
R23 "100" SMD_RES_0603 77.597,30.607 r180 top
R24 "50" SMD_RES_0603 60.325,49.657 r180 top
R25 "50" SMD_RES_0603 60.325,47.371 r180 top
R26 "50" SMD_RES_0603 38.862,37.338 r270 top
R27 "50" SMD_RES_0603 41.148,37.338 r270 top
R28 "50" SMD_RES_0603 66.167,28.829 r270 top
R29 "50" SMD_RES_0603 67.818,28.829 r270 top
R30 "50" SMD_RES_0603 60.325,49.276 r0 bottom
R31 "50" SMD_RES_0603 39.37,37.338 r90 bottom
R32 "50" SMD_RES_0603 66.294,28.829 r90 bottom
TP1 "Test Pin" PIn_1mm 33.02,3.683 r0 top
TP2 "Test Pin" PIn_1mm 57.023,3.81 r0 top
TP3 "Test Pin" PIn_1mm 12.827,3.683 r0 top
TP4 "Test Pin" PIn_1mm 67.183,3.81 r0 top
TP5 "Test Pin" PIn_1mm 17.78,3.683 r0 top
TP6 "Test Pin" PIn_1mm 27.94,3.683 r0 top
TP7 "Test Pin" PIn_1mm 62.103,3.81 r0 top
TP8 "Header_2pin_1row_1.27" HDRV2W40P0X127_1X2_254X210X420P 40.386,44.069 r270 bottom
TP9 "Test Pin" PIn_1mm 22.86,3.683 r0 top
TP10 "Header_2pin_1row_1.27" HDRV2W40P0X127_1X2_254X210X420P 68.199,42.037 r0 bottom
TP11 "Header_2pin_1row_1.27" HDRV2W40P0X127_1X2_254X210X420P 69.342,49.149 r270 bottom
TP12 "Header_2pin_1row_1.27" HDRV2W40P0X127_1X2_254X210X420P 40.259,33.655 r0 bottom
TP13 "Header_2pin_1row_1.27" HDRV2W40P0X127_1X2_254X210X420P 57.277,49.149 r270 bottom
TP14 "Header_2pin_1row_1.27" HDRV2W40P0X127_1X2_254X210X420P 78.232,33.147 r180 bottom
U1 "MAX4014" SMD_SOT-23-5 63.754,13.462 r90 top
U2 "AD8065" SMD_SOT-23-5 18.669,13.462 r90 top
U3 "AM2DM - DH" AM2DM_dual_3 51.816,74.422 r0 top
U4 "AP2204K-3.3TRG1" SMD_SOT-23-5 70.612,54.229 r270 top
U5 "L78L05ACUTR" SOT-89_N 11.303,50.635 r90 top
U6 "L79L05ACUTR" SOT-89_N 11.303,56.807 r270 top
U7 "ADCMP582" QFN50P300X300X80-17N-D 29.984,34.618 r0 top
U8 "MCP6001" SMD_SOT-23-5 20.066,27.178 r90 top
U9 "SN65LVDS2D" SMD_SOIC-8 63.7,38.481 r180 top
U10 "MC100LVEL05" SMD_SOIC-8 44.577,42.164 r0 top
U11 "SN65LVDS20DRFT" SON50P200X200X80-9N-D 64.008,48.514 r0 top
U12 "SY100EL29VZG" SOIC127P1030X265-20N 58.547,28.829 r90 top
U13 "MAX9375" SOP65P490X110-8N 73.025,27.051 r180 top

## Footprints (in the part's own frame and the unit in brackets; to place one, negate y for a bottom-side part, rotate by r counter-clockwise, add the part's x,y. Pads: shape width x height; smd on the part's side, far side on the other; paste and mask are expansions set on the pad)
61300211121 [mm] "2 pins, 1 row, straight, gold plating"
  rect 1.6x1.6 hole 1.1: 1(0,0)
  round 1.6 hole 1.1: 2(2.54,0)
  silkscreen extent -1.27,-1.27 3.81,1.27, body extent -1.27,-1.27 3.81,1.27, height 8.54
AM2DM_dual_3 [mil]
  round 60 hole 30: 1(0,0) 2(100,0) 5(400,0) 6(500,0) 7(600,0)
  silkscreen extent -84,-260 684,155, body extent -84,-260 684,126, height 492
HDRV2W40P0X127_1X2_254X210X420P [mm]
  rect 1x1 hole 0.6: 1(0,0)
  round 1 hole 0.6: 2(1.27,0)
  silkscreen extent -0.88,-1.1 2.15,1.1, body extent -0.64,-1.05 1.91,1.05, height 4
PIn_1mm [mm]
  round 1.8 hole 1: 1(0,0)
  silkscreen extent -1.2,-1.2 1.2,1.2, body extent -1,-1 1,1, height 4.6
QFN50P300X300X80-17N-D [mm]
  rect 0.85x0.3 smd: 1(-1.45,0.75) 2(-1.45,0.25) 3(-1.45,-0.25) 4(-1.45,-0.75) 9(1.45,-0.75) 10(1.45,-0.25) 11(1.45,0.25) 12(1.45,0.75)
  rect 0.3x0.85 smd: 5(-0.75,-1.45) 6(-0.25,-1.45) 7(0.25,-1.45) 8(0.75,-1.45) 13(0.75,1.45) 14(0.25,1.45) 15(-0.25,1.45) 16(-0.75,1.45)
  rect 1.45x1.45 smd: 17(0,0)
  silkscreen extent -2,1.38 -1.75,1.62, body extent -1.55,-1.55 1.55,1.55, height 0.8
SHDR2W165P0X396_1X2_716X1062X1425P [mm]
  rect 3x3 hole 1.8: 1(0,0)
  round 3 hole 1.8: 2(3.96,0)
  silkscreen extent -1.75,-5.65 5.71,5.6, body extent -1.58,-5.6 5.58,5.15, height 13.85
SMA5.08-H [mm] "Connector; RF Coaxial, MCX, Thru-Hole; 5 Position; Right Angle"
  round 2.4 hole 1.5: 1(0,0)
  round 2.8 hole 1.7: 2(-2.54,-2.54) 3(2.54,-2.54) 4(2.54,2.54) 5(-2.54,2.54)
  silkscreen extent -3,-3 3,3, body extent -6.5,-3 3,3, height 5.99
SMD_CAP_POL_D5.0mm [mm]
  rect 3x1.8 smd: 1(-2.55,0) 2(2.55,0)
  silkscreen extent -4.05,-2.65 2.65,2.65, body extent -3.25,-2.75 3.25,2.75, height 6.1
SMD_CAPACITOR_0603 [mm]
  rect 0.87x1.02 smd: 1(-0.68,0) 2(0.68,0)
  body extent -0.8,-0.4 0.8,0.4, height 1
SMD_CAPACITOR_1206 [mm]
  rect 1.52x1.6 smd: 1(-1.71,0) 2(1.71,0)
  silkscreen extent -0.7,-0.8 0.7,0.8, body extent -1.6,-0.8 1.6,0.8, height 1.58
SMD_CAPACITOR_POL_A_3216 [mm]
  rect 1.8x1.25 smd: 1(-1.3,0) 2(1.3,0)
  silkscreen extent -2.15,-0.89 1.5,0.89, body extent -1.6,-0.8 1.6,0.8, height 1.8
SMD_INDUCTOR_7.3MM [mm]
  rect 2.1x2.8 smd: 1(-3.45,0) 2(3.45,0)
  silkscreen extent -3.65,-3.65 3.65,3.65, body extent -3.65,-3.65 3.65,3.65, height 4
SMD_LED_0603 [mm]
  rect 1.2x0.7 smd: 1(0.75,0) 2(-0.75,0)
  silkscreen extent -1.2,-0.51 0.8,0.51, body extent -0.8,-0.4 0.8,0.4, height 0.36
SMD_RES_0603 [mm]
  rect 0.9x1 smd: 1(-0.75,0) 2(0.75,0)
  body extent -0.75,-0.4 0.8,0.4, height 0.55
SMD_RESISTOR_0805 [mm]
  rect 1.14x1.27 smd: 1(-1.015,0) 2(1.015,0)
  silkscreen extent -0.2,-0.64 0.2,0.64, body extent -1,-0.64 1,0.64, height 0.61
SMD_RESISTOR_1206 [mm]
  rect 1.52x1.6 smd: 1(-1.71,0) 2(1.71,0)
  silkscreen extent -0.7,-0.8 0.7,0.8, body extent -1.6,-0.81 1.6,0.81, height 0.61
SMD_SOD-123 [mm]
  rect 0.91x1.2 smd: 1(-1.635,0) 2(1.635,0)
  silkscreen extent -0.9,-0.8 0.9,0.8, body extent -1.65,-0.8 1.65,0.8, height 1.2
SMD_SOD-323 [mm]
  rect 1.088x0.55 smd: 1(1.158,0) 2(-1.158,0)
  silkscreen extent -1.7,-0.64 0.82,0.64, body extent -1.29,-0.64 1.29,0.64, height 1.17
SMD_SOIC-8 [mm]
  rect 1.78x0.72 smd: 1(-2.34,1.905) 2(-2.34,0.635) 3(-2.34,-0.635) 4(-2.34,-1.905) 5(2.34,-1.905) 6(2.34,-0.635) 7(2.34,0.635) 8(2.34,1.905)
  silkscreen extent -3.94,-2.5 2,2.5, body extent -2,-2.5 2,2.5, height 1.44
SMD_SOT-23-5 [mm]
  rect 0.65x1.1 smd: 1(-0.95,-1.1) 2(0,-1.1) 3(0.95,-1.1) 4(0.95,1.1) 5(-0.95,1.1)
  silkscreen extent -1.5,-0.7 1.5,0.7, body extent -1.45,-1.4 1.45,1.4, height 1.45
SOIC127P1030X265-20N [mm]
  rect 1.925x0.7 smd: 1(-4.712,5.715) 2(-4.712,4.445) 3(-4.712,3.175) 4(-4.712,1.905) 5(-4.712,0.635) 6(-4.712,-0.635) 7(-4.712,-1.905) 8(-4.712,-3.175) 9(-4.712,-4.445) 10(-4.712,-5.715) 11(4.712,-5.715) 12(4.712,-4.445) 13(4.712,-3.175) 14(4.712,-1.905) 15(4.712,-0.635) 16(4.712,0.635) 17(4.712,1.905) 18(4.712,3.175) 19(4.712,4.445) 20(4.712,5.715)
  silkscreen extent -5.68,-6.35 3.4,6.42, body extent -5.15,-6.35 5.15,6.35, height 2.65
SOLDER_BRIDGE_1MM [mm]
  rect 1x1 smd mask+0.07: 1(-0.625,0) 2(0.625,0)
SOLDER_BRIDGE_2MM [mm]
  rect 2x2 smd mask+0.05: 1(-1.125,0) 2(1.125,0)
SON50P200X200X80-9N-D [mm]
  rect 0.85x0.3 smd mask+0.04: 1(-0.95,0.75) 2(-0.95,0.25) 3(-0.95,-0.25) 4(-0.95,-0.75) 5(0.95,-0.75) 6(0.95,-0.25) 7(0.95,0.25) 8(0.95,0.75)
  rect 0.525x1.825 smd mask+0.06: 9(0,0)
  silkscreen extent -1.5,1.28 -1.25,1.52, body extent -1.05,-1 1.05,1, height 0.8
SOP65P490X110-8N [mm]
  rect 1.425x0.45 smd: 1(-2.212,0.975) 2(-2.212,0.325) 3(-2.212,-0.325) 4(-2.212,-0.975) 5(2.212,-0.975) 6(2.212,-0.325) 7(2.212,0.325) 8(2.212,0.975)
  silkscreen extent -2.93,-1.5 1.15,1.55, body extent -2.45,-1.5 2.45,1.5, height 1.1
SOT-89_N [mm] "SOT89, 3-Leads, Body 4.5x2.4 mm, Pitch 1.5mm, Lead Span 4.1mm, IPC Medium Density"
  rect 1.4x0.6 smd: 1(-1.9,1.5) 3(-1.9,-1.5)
  rect 1.8x0.6 smd: 2(-1.7,0)
  oct 3.3x1.9 smd: 2(0.8,0)
  silkscreen extent -2.07,-2.3 1.3,2.47, body extent -1.3,-2.3 1.3,2.3, height 1.6
THT_HEADER_100MIL_2X3_MALE_SHROUDED [mm]
  round 1.4 hole 0.9: 1(-1.27,2.54) 2(1.27,2.54) 3(-1.27,0) 4(1.27,0) 5(-1.27,-2.54) 6(1.27,-2.54)
  silkscreen extent -4.25,-7.65 4.3,7.65, body extent -4.6,-7.61 4.25,7.61, height 9.33
THT_TRIM_3296Y1502LF [mm]
  round 1.2 hole 0.75: 1(0,0) 2(-2.54,2.54) 3(0,5.08)
  silkscreen extent -3.68,-2.22 1.8,7.3, body extent -3.68,-2.22 1.14,7.31, height 10.13

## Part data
C1 C2 C3 C4 C5 C6 C7 C8 C9 C10 C11 C12 C13 C14 C15 C17 C18 C19 C20 C22 C23 C24 C25 C27 C28 C29 C30 C32 C33 C34 C35 C36 C37 C40 C41 C42 C43 C44 C45 C47 C48 C49 C50 C51 C52 C53 C54 C55 C56 C57 C58 C59 C60 C61 C62 C63 C64 C65 C66 C67 C68 C69 C70 C71 C72 C73 C74 C75 C76 C77 C78 C79 C80 C81 C82 C83 C84 C85 C86 C87 C88 C89 C90: library part Capacitor
C16 C21 C26 C31 C38 C39 C46: library part Capacitor_pol
D1: library part Diode
D2: library part TVS_Diode_unidirect
D3 D4: library part LED
J1 J2 J3 J5 J9: library part Solder_Bridge_1mm
J4 J14 J17: library part Solder_Bridge_2mm
J6 J7 J8 J10 J11 J12 J13 J15 J16: Manufacturer="Wurth Electronics", Package="2-pin, 2.54 mm", Part Number=61300211121
L1 L2 L3 L4 L9 L10 L11 L12 L13: library part EMI_Ferrite_bead
L5 L6 L7 L8: library part Inductor
P1 P2: "Connector", Manufacturer_Name=Molex, Mouser Part Number=538-09-65-2028, RS Part Number=6705237P
P3 P6: library part Header_2x3
R1 R2 R3 R4 R5 R6 R7 R8 R9 R10 R11 R12 R13 R14 R16 R17 R18 R19 R20 R21 R22 R23 R24 R25 R26 R27 R28 R29 R30 R31 R32: library part Resistor
R15: library part Resistor_trim
TP1 TP2 TP3 TP4 TP5 TP6 TP7 TP9: "Connector"
TP8 TP10 TP11 TP12 TP13 TP14: Manufacturer=Harwin, Package="2-pin, 1.27 mm", Part Number=M50-3530242
U7: "Ultrafast Differential Comparator"
U9: "SINGLE LVDS RECEIVER"
U10: "3.3 V ECL 2-Input Differential AND/NAND"
U11: "LVPECL AND LVDS REPEATER/TRANSLATOR WITH ENABLE"
U12: "Dual Differential Data and Clock D Flip-Flop withSet and Reset"
U13: "Single LVDS/Anything-to-LVPECL Translator"

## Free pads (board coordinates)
  round 8 hole 3.2: 2(5,5) 2(5,75) 2(75,5) 2(75,75)

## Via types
v1: diameter 0.5, hole 0.2, Component Side to Bottom Layer, 398 vias

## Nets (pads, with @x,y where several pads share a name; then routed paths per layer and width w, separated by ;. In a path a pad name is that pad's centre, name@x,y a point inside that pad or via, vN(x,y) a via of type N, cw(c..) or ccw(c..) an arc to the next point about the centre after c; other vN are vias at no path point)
+3V3-D: C25.2 C26.1 C58.1 C60.1 C62.1 C64.1 C66.1 C68.1 C73.1 C74.1 C75.1 C76.1 C77.1 C78.1 C79.1 C80.1 C81.1 C82.1 C83.1 C84.1 C85.1 C86.1 C87.1 P3.2 R19.1 U4.5 U7.9 U7.12 U9.8 U10.8 U11.8 U12.10 U12.14 U12.19 U13.1 U13.8 | length 133.6
  Component Side w0.254: U7.9@31.434,33.868 32.127,33.868 C68.1@33.864,32.131 ; U7.12@31.434,35.368 33.799,35.368 C62.1@33.864,35.433 ; U11.8@64.958,49.264 65.139,49.264 65.532,49.657 v1(65.786,49.657) v1(66.421,49.657) ; v1(68.875,26.076) v1(69.51,26.076) U13.8@70.813,26.076 ; v1(74.295,26.035) 75.196,26.035 U13.1@75.237,26.076
  Component Side w0.508: v1(31.877,27.813) v1(31.877,28.448) R19.1@31.877,29.476 ; v1(33.782,26.543) v1(33.782,27.305) v1(33.782,28.067) 33.782,29.001 C64.1@33.864,29.083 C66.1@33.864,30.607 C68.1@33.864,32.131 ; v1(33.782,40.767) v1(33.782,40.132) v1(33.782,39.497) 33.782,38.563 C58.1@33.864,38.481 C60.1@33.864,36.957 C62.1@33.864,35.433 ; U10.8@46.917,44.069 v1(48.26,44.069) v1(48.895,44.069) ; U12.19@54.102,33.541 54.102,34.925 54.737,35.56 59.817,35.56 60.452,34.925 U12.14@60.452,33.541 60.452,27.432 61.468,26.416 v1(62.865,26.416) v1(63.5,26.416) 64.262,25.654 U12.10@64.262,24.117 ; U9.8@61.541,36.576 62.103,36.576 62.992,35.687 v1(63.373,35.687) v1(64.135,35.687) ; U4.5@71.943,55.179 U4.5@71.712,55.179 72.771,56.238 C25.2@72.771,56.851 73.578,56.851 74.198,56.231 C26.1@75.039,56.107
  Component Side w1.016: v1(75.057,52.705) v1(75.057,53.34) v1(75.057,53.975) v1(75.057,54.61) C26.1@75.057,56.231
  Bottom Layer w0.254: P3.2@6.223,37.465 6.223,41.783 7.743,43.303 33.151,43.303 v1(33.782,42.672) v1(33.782,42.037) ; C84.1@71.501,27.26 72.726,26.035 v1(74.295,26.035)
  Bottom Layer w0.508: v1(48.387,39.224) v1(47.689,39.224) C75.1@46.273,40.64 C78.1@46.273,42.164 C81.1@46.273,43.688 46.654,44.069 v1(48.26,44.069) v1(48.895,44.069) ; C80.1@62.185,36.801 63.299,35.687 v1(63.373,35.687) v1(64.135,35.687) ; C80.1@62.185,36.957 C77.1@62.185,38.481 C74.1@62.185,40.005 62.185,40.341 v1(63.246,41.402) v1(63.754,41.91) ; v1(62.865,26.416) C87.1@61.767,26.416 C86.1@61.767,27.94 C85.1@61.767,29.464 v1(62.865,29.464) v1(63.5,29.464) ; v1(66.421,49.657) v1(65.786,49.657) 65.069,49.657 C79.1@64.688,49.276 C76.1@64.688,47.879 C73.1@64.688,46.355 v1(65.913,46.355) v1(66.548,46.355) ; v1(68.875,26.076) v1(69.51,26.076) 70.317,26.076 C84.1@71.501,27.26 C83.1@73.025,27.26 C82.1@74.549,27.26 74.93,26.879 74.93,25.019 75.184,24.765 v1(75.311,24.765) v1(76.073,24.765)
+5V-A: C36.2 C37.2 C38.1 L1.2 L2.2 L9.2 L11.2 P3.1 R13.2 R15.3 U5.1 | length 27.9
  Component Side w0.508: P3.1@3.683,37.465 3.683,43.942 v1(4.318,44.577) v1(4.826,45.085) ; v1(6.432,47.894) v1(5.797,47.894) v1(5.162,47.894) v1(4.527,47.894) 4.303,47.894 3.81,48.387 C38.1@3.81,49.47 3.825,49.485 C37.2@5.969,49.485 C36.2@7.493,49.485 8.243,48.735 U5.1@9.803,48.735 ; L2.2@14.986,9.513 v1(14.986,10.668) v1(14.986,11.43) ; L9.2@16.383,23.229 v1(16.383,24.384) v1(16.383,25.146) ; R13.2@19.558,35.675 v1(19.558,36.83) v1(19.558,37.592) ; v1(28.956,23.368) v1(28.956,24.13) L11.2@28.956,25.285 ; L1.2@60.071,9.513 v1(60.071,10.668) v1(60.071,11.43)
-5V-A: C44.2 C45.2 C46.2 L3.1 L4.1 L10.1 L13.1 P3.5 R14.1 R15.1 U6.3 | length 31.7
  Component Side w0.508: v1(3.81,61.341) v1(3.81,60.706) v1(3.81,60.071) v1(3.81,59.436) C46.2@3.81,57.972 3.825,57.957 C45.2@5.969,57.957 C44.2@7.493,57.957 8.243,58.707 U6.3@9.803,58.707 ; R14.1@21.209,35.675 21.209,38.1 18.796,40.513 R15.1@18.796,41.656 23.876,41.656 v1(24.765,40.767) v1(25.388,40.767) v1(26.023,40.767) v1(26.67,40.767) L13.1@27.698,40.767 ; L3.1@23.622,9.513 v1(23.622,10.668) v1(23.622,11.43) ; L10.1@25.019,23.229 v1(25.019,24.384) v1(25.019,25.146) ; L4.1@68.707,9.501 v1(68.707,10.656) v1(68.707,11.418)
AGND: C1.2 C2.2 C3.2 C4.2 C5.2 C6.2 C7.2 C8.1 C9.2 C10.2 C11.2 C12.2 C13.2 C31.2 C32.1 C33.1 C34.1 C35.1 C36.1 C37.1 C38.2 C39.1 C40.1 C41.1 C42.1 C43.1 C44.1 C45.1 C46.1 C47.2 C48.2 C49.2 C50.1 C51.1 C52.2 C53.2 C55.1 C56.1 C57.2 C59.2 C61.2 C63.2 C65.2 C67.2 C69.2 C70.2 C71.2 C72.1 P3.6 P4.2 P4.3 P4.4 P4.5 P5.2 P5.3 P5.4 P5.5 R5.1 R6.1 R7.1 R9.2 R16.1 TP5.1 TP6.1 TP7.1 U5.2 U6.1 U7.1 | length 0.3
  Component Side w0.254: U7.1@28.259,35.368 U7.1@28.534,35.368
  other v1: 18.923,8.001 19.685,8.001 64.008,8.001 64.77,8.001 18.923,8.763 19.685,8.763 64.008,8.763 64.77,8.763 18.923,9.525 19.685,9.525 64.008,9.525 64.77,9.525 18.923,10.287 19.685,10.287 64.008,10.287 64.77,10.287 18.923,11.049 19.685,11.049 64.008,11.049 64.77,11.049 10.668,13.462 11.303,13.462 12.192,13.462 14.097,14.224 14.097,14.859 20.447,17.526 65.532,17.526 20.447,18.288 65.532,18.288 20.32,21.717 21.082,21.717 20.32,22.479 21.082,22.479 20.32,23.241 21.082,23.241 20.32,24.003 21.082,24.003 20.32,24.765 21.082,24.765 8.636,26.162 9.398,26.162 26.67,28.448 26.67,29.21 18.415,29.464 26.67,29.972 18.415,30.099 26.67,30.734 18.415,30.988 25.527,31.496 26.67,31.496 18.415,31.623 26.289,36.703 26.924,36.703 27.559,36.703 32.893,37.719 32.893,38.481 22.987,38.862 23.749,38.862 24.511,38.862 25.273,38.862 25.908,38.862 32.893,39.243 25.908,39.624 32.893,40.005 32.893,40.767 10.668,47.371 11.303,47.371 11.938,47.371 14.732,50.927 15.494,50.927 16.256,50.927 17.018,50.927 24.13,51.054 27.178,51.054 15.113,51.435 15.875,51.435 16.637,51.435 5.588,51.816 6.35,51.816 7.112,51.816 7.874,51.816 24.13,51.816 27.178,51.816 5.969,52.324 6.731,52.324 7.493,52.324 18.034,52.578 18.669,52.578 19.304,52.578 20.32,52.578 20.955,52.578 21.59,52.578 24.13,52.578 27.178,52.578 32.639,53.086 33.274,53.086 3.048,53.721 3.81,53.721 4.572,53.721 24.892,53.721 25.654,53.721 26.416,53.721 32.639,53.721 33.274,53.721 32.639,54.356 33.274,54.356 18.034,54.864 18.669,54.864 19.304,54.864 20.32,54.864 20.955,54.864 21.59,54.864 24.13,54.864 27.178,54.864 5.969,55.118 6.731,55.118 7.493,55.118 5.588,55.626 6.35,55.626 7.112,55.626 7.874,55.626 24.13,55.626 27.178,55.626 15.113,56.007 15.875,56.007 16.637,56.007 24.13,56.388 27.178,56.388 14.732,56.515 15.494,56.515 16.256,56.515 17.018,56.515 13.97,58.674 13.97,59.309 12.827,60.071 13.462,60.071
AndIN_N: J11.1 J13.1 J16.1 R27.1 TP12.2 U10.4 | length 25
  Component Side w0.19: U10.4@42.237,40.259 41.252,40.259 40.867,40.644 40.513,40.644 40.259,40.39 40.259,38.977 R27.1@41.148,38.088 40.255,37.195 40.255,35.763 41.017,35.001 41.144,34.874 41.144,34.04 TP12.2@41.529,33.655 41.144,33.27 41.144,31.623 41.144,31.433 41.144,31.053 41.144,30.992 41.278,30.858 41.547,30.589 41.816,30.32 41.851,30.285 42.041,30.285 42.23,30.285 ccw(c42.23,30.475) 42.42,30.475 42.42,31.156 cw(c42.61,31.156) 42.61,31.346 cw(c42.61,31.156) 42.8,31.156 42.8,30.475 ccw(c42.99,30.475) 42.99,30.285 43.239,30.285 J13.1@44.577,31.623 J16.1@44.577,34.544 J11.1@44.577,37.465
AndIN_P: J10.1 J12.1 J15.1 R26.1 TP12.1 U10.3 | length 25
  Component Side w0.19: U10.3@42.142,41.434 U10.3@42.237,41.529 41.252,41.529 40.867,41.144 40.306,41.144 39.759,40.597 39.759,38.985 R26.1@38.862,38.088 39.755,37.195 39.755,35.556 40.644,34.667 40.644,34.04 TP12.1@40.259,33.655 40.644,33.27 40.644,30.785 41.643,29.786 43.239,29.786 J12.1@44.577,28.448 J15.1@44.577,25.527 J10.1@44.577,22.606
AndOut_N: J17.2 R25.1 TP13.2 U10.6 U11.3 | length 26.6
  Component Side w0.19: U10.6@46.917,41.529 47.902,41.529 48.287,41.914 50.495,41.914 51.281,42.699 51.427,42.846 51.427,44.276 50.165,45.538 50.165,48.006 50.423,48.264 54.667,48.264 54.973,47.958 J17.2@54.973,46.863 56.374,48.264 56.892,48.264 TP13.2@57.277,47.879 57.662,48.264 60.182,48.264 R25.1@61.075,47.371 61.968,48.264 U11.3@63.058,48.264
AndOut_P: J14.2 R24.1 TP13.1 U10.7 U11.2 | length 26.6
  Component Side w0.19: U10.7@46.917,42.799 47.902,42.799 48.287,42.414 50.288,42.414 50.927,43.053 50.927,44.069 49.665,45.331 49.665,48.213 49.811,48.36 50.216,48.764 54.667,48.764 54.973,49.07 J14.2@54.973,50.165 56.374,48.764 56.892,48.764 TP13.1@57.277,49.149 57.662,48.764 60.182,48.764 R24.1@61.075,49.657 61.968,48.764 U11.2@63.058,48.764
Comp_Out_N: R18.1 TP8.2 U7.10 U10.2 | length 22
  Component Side w0.19: U7.10@31.434,34.368 32.18,34.368 32.885,33.663 36.275,33.663 37.465,34.853 37.465,39.191 36.699,39.957 36.699,41.132 R18.1@37.592,42.025 36.969,42.025 36.703,42.291 36.703,42.672 37.215,43.184 40.001,43.184 TP8.2@40.386,42.799 U10.2@42.237,42.799
Comp_Out_P: R17.1 TP8.1 U7.11 U10.1 | length 22
  Component Side w0.19: U7.11@31.434,34.868 32.387,34.868 33.092,34.163 36.068,34.163 36.965,35.06 36.965,38.984 36.199,39.75 36.199,41.114 R17.1@35.306,42.007 35.919,42.007 36.203,42.291 36.203,42.879 36.349,43.026 37.008,43.684 40.001,43.684 TP8.1@40.386,44.069 U10.1@42.237,44.069
DGND: C21.2 C22.1 C23.1 C24.1 C25.1 C26.2 C54.1 C58.2 C60.2 C62.2 C64.2 C66.2 C68.2 C73.2 C74.2 C75.2 C76.2 C77.2 C78.2 C79.2 C80.2 C81.2 C82.2 C83.2 C84.2 C85.2 C86.2 C87.2 C88.1 C89.1 C90.1 P3.4 R10.2 R20.2 R30.2 R31.2 R32.2 U4.2 U7.15 U7.17 U9.5 U10.5 U11.5 U11.9 U12.6 U12.7 U12.8 U12.9 U12.11 U12.15 U12.16 U13.4 U13.5 | length 39.7
  Component Side w0.254: U7.15@29.734,36.068 29.734,34.868 v1(29.984,34.618) ; U11.9@64.008,47.764 U11.5@64.958,47.764
  Bottom Layer w0.254: P3.4@6.223,34.925 4.953,36.195 4.953,41.084 7.576,43.707 33.763,43.707 v1(34.163,43.307)
  other v1: 59.309,25.654 62.992,25.654 59.309,26.416 59.309,27.178 59.309,27.94 59.309,28.702 69.723,28.829 70.358,28.829 75.692,28.829 76.327,28.829 36.068,29.083 59.309,29.464 71.501,29.718 72.263,29.718 73.025,29.718 73.787,29.718 74.549,29.718 36.068,29.845 64.389,30.099 65.024,30.099 68.961,30.099 36.068,30.607 66.675,30.607 68.961,30.734 36.068,31.369 57.912,31.877 58.547,31.877 59.182,31.877 64.262,31.877 36.068,32.131 29.566,34.214 30.404,34.214 29.591,35.052 30.378,35.052 36.068,35.433 36.068,36.195 36.068,36.957 64.643,36.957 36.068,37.719 64.643,37.719 42.291,38.227 36.068,38.481 64.643,38.481 42.291,38.862 39.116,39.243 41.021,39.243 64.643,39.243 48.387,39.878 64.643,40.005 38.862,40.64 43.942,40.64 48.387,40.64 38.862,41.275 43.942,41.402 61.722,41.402 38.862,41.91 61.722,42.037 43.942,42.164 43.942,42.926 34.925,43.18 35.56,43.18 43.942,43.688 62.357,45.72 60.96,46.228 61.595,46.228 62.357,46.355 62.357,46.99 65.913,47.371 66.548,47.371 62.484,49.911 62.484,50.546 60.833,50.8 61.468,50.8 68.326,53.467 68.326,54.229 63.119,54.991 66.167,54.991 68.326,54.991 56.642,55.118 57.277,55.118 56.642,55.753 57.277,55.753 63.119,55.753 66.167,55.753 56.642,56.388 57.277,56.388 63.119,56.515 66.167,56.515 71.628,56.515 71.628,57.277 71.628,58.039 71.628,58.801 72.39,59.309 73.152,59.309 74.041,60.706 74.803,60.706 75.565,60.706 74.041,61.341 74.041,61.976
